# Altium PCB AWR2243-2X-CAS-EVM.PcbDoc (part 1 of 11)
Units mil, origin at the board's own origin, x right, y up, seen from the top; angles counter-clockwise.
Board outline 5118.11 x 3937.01 mil, 8 copper layers (Layer 1 - Top Layer, Layer 2 - GND, Layer 3 - Signal (Sensitive), Layer 4 - GND / Signal, Layer 5 - Signal, Layer 6 - PWR / Signal, Layer 7 - GND, Layer 8 - Bottom Layer), stack 54.8 mil thick; 629 components, 407 nets, 2243 pads, 3950 vias.
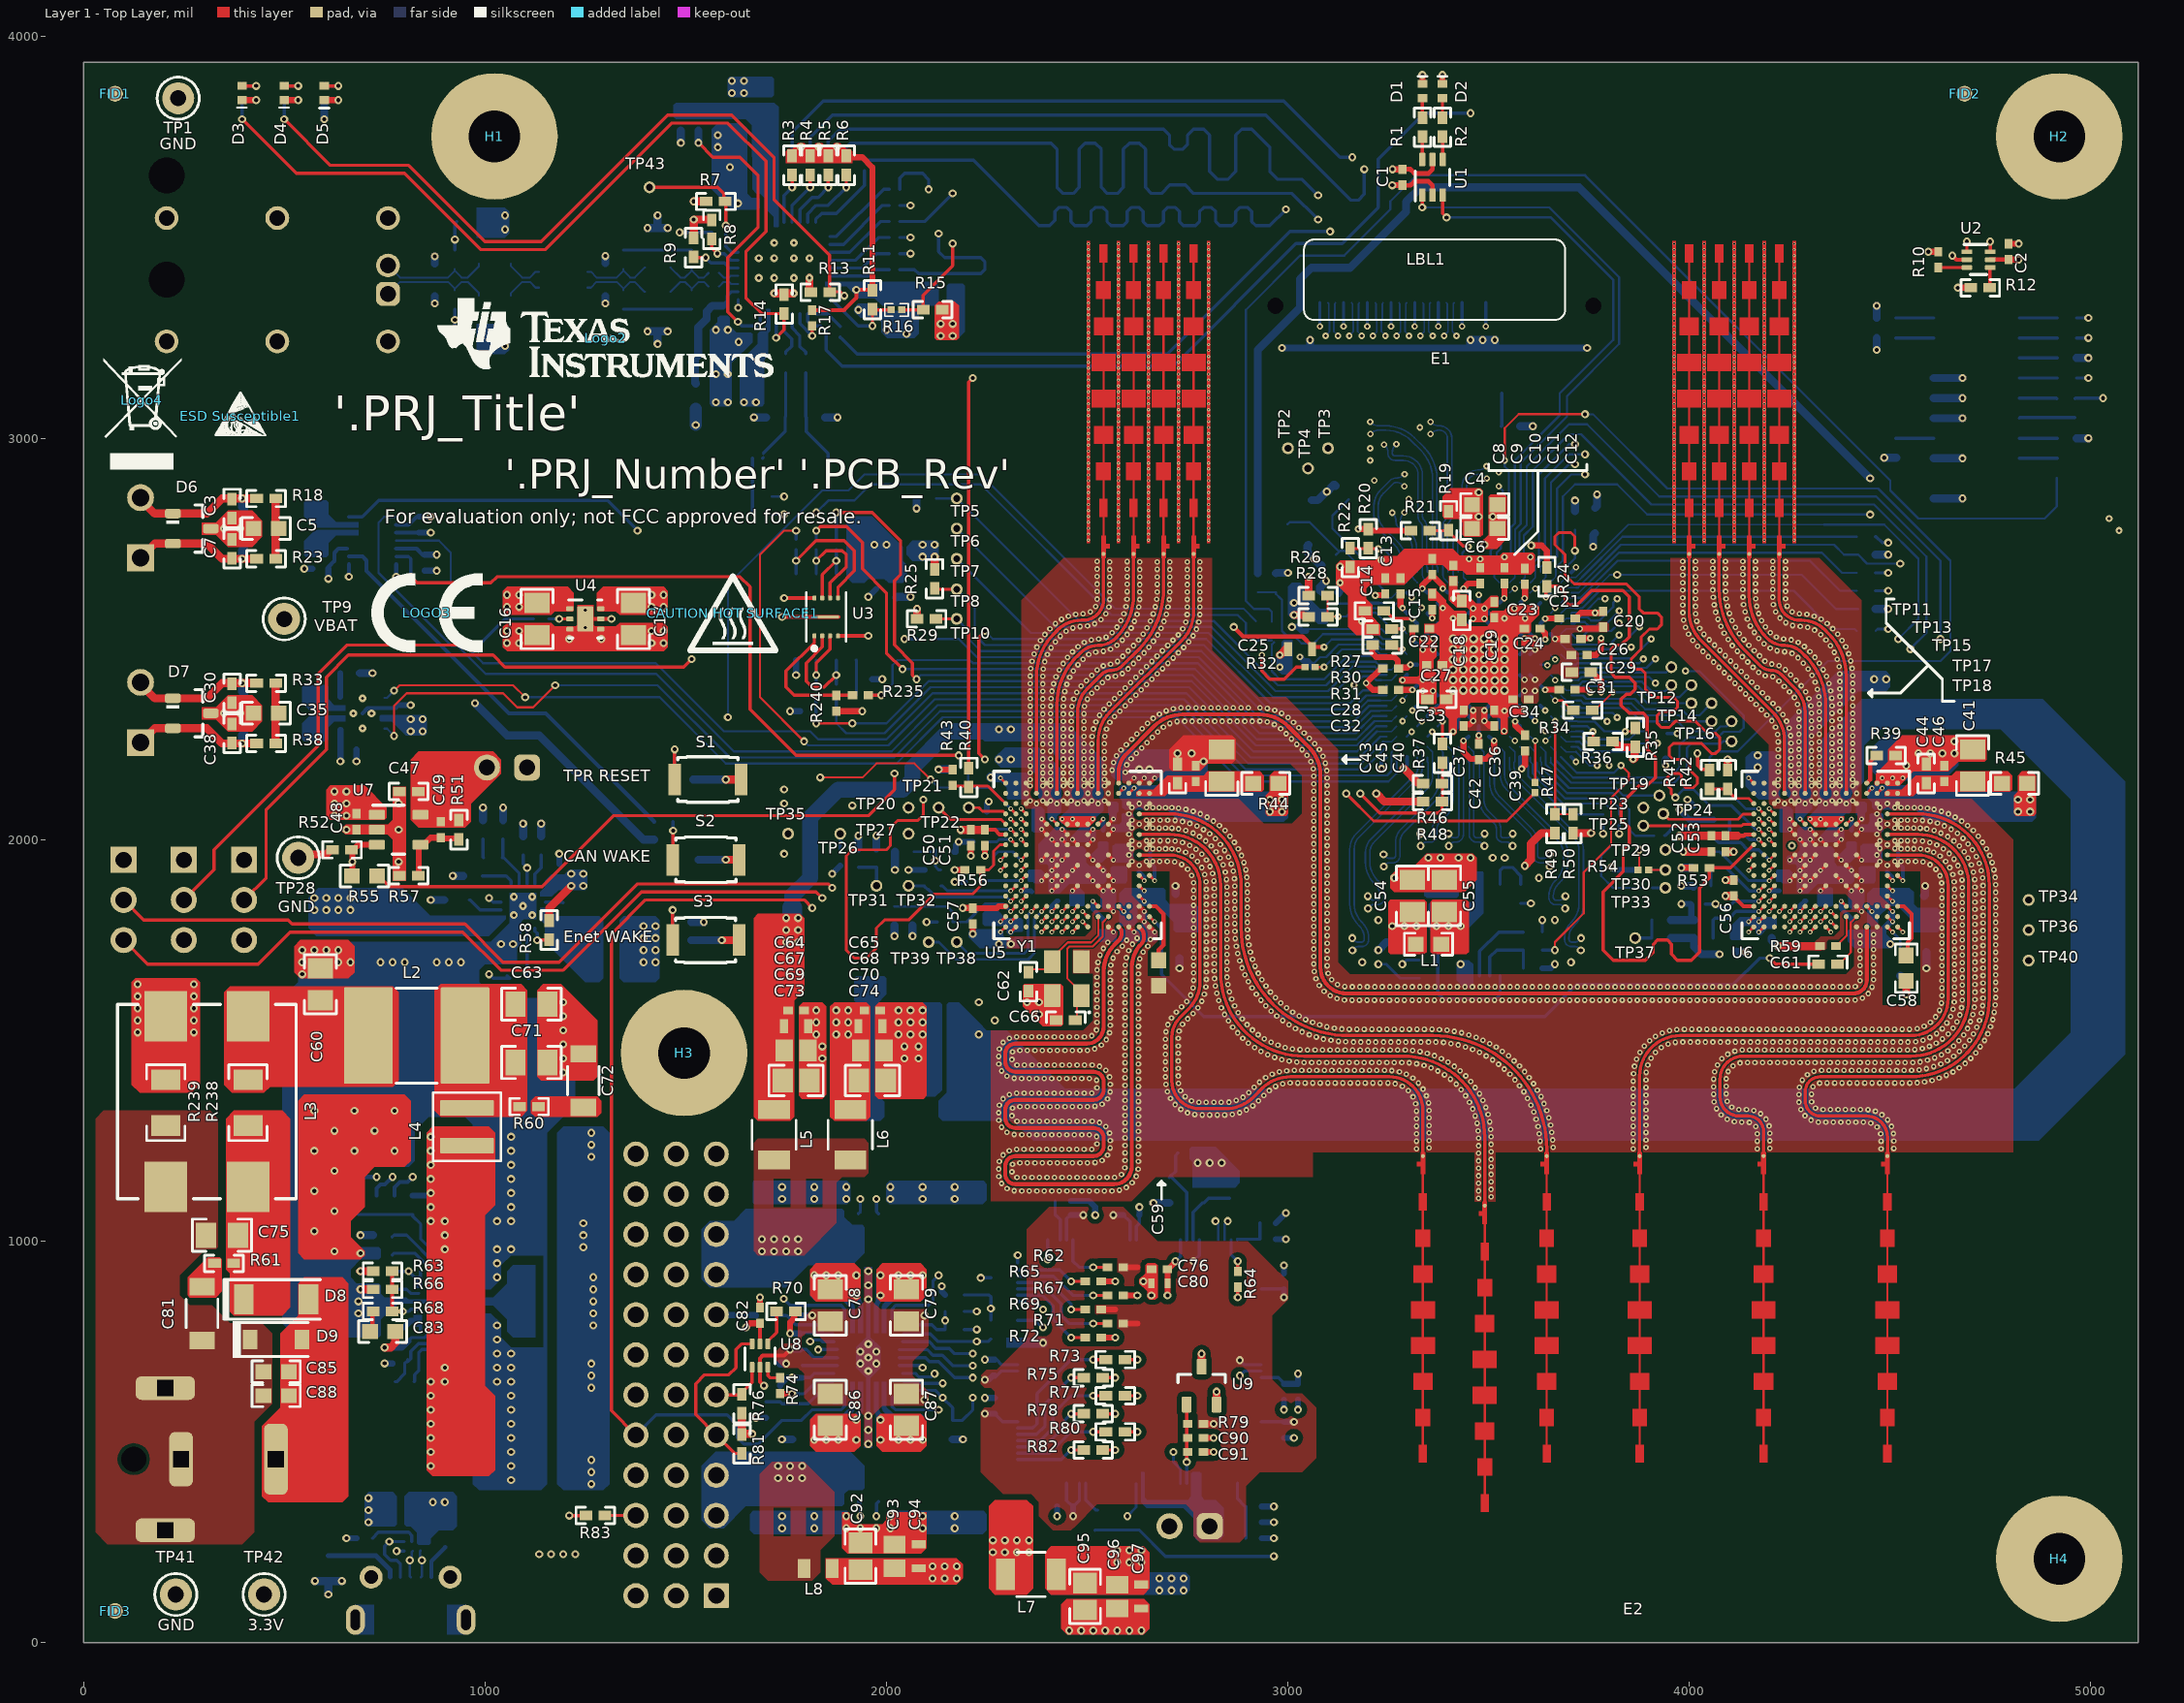
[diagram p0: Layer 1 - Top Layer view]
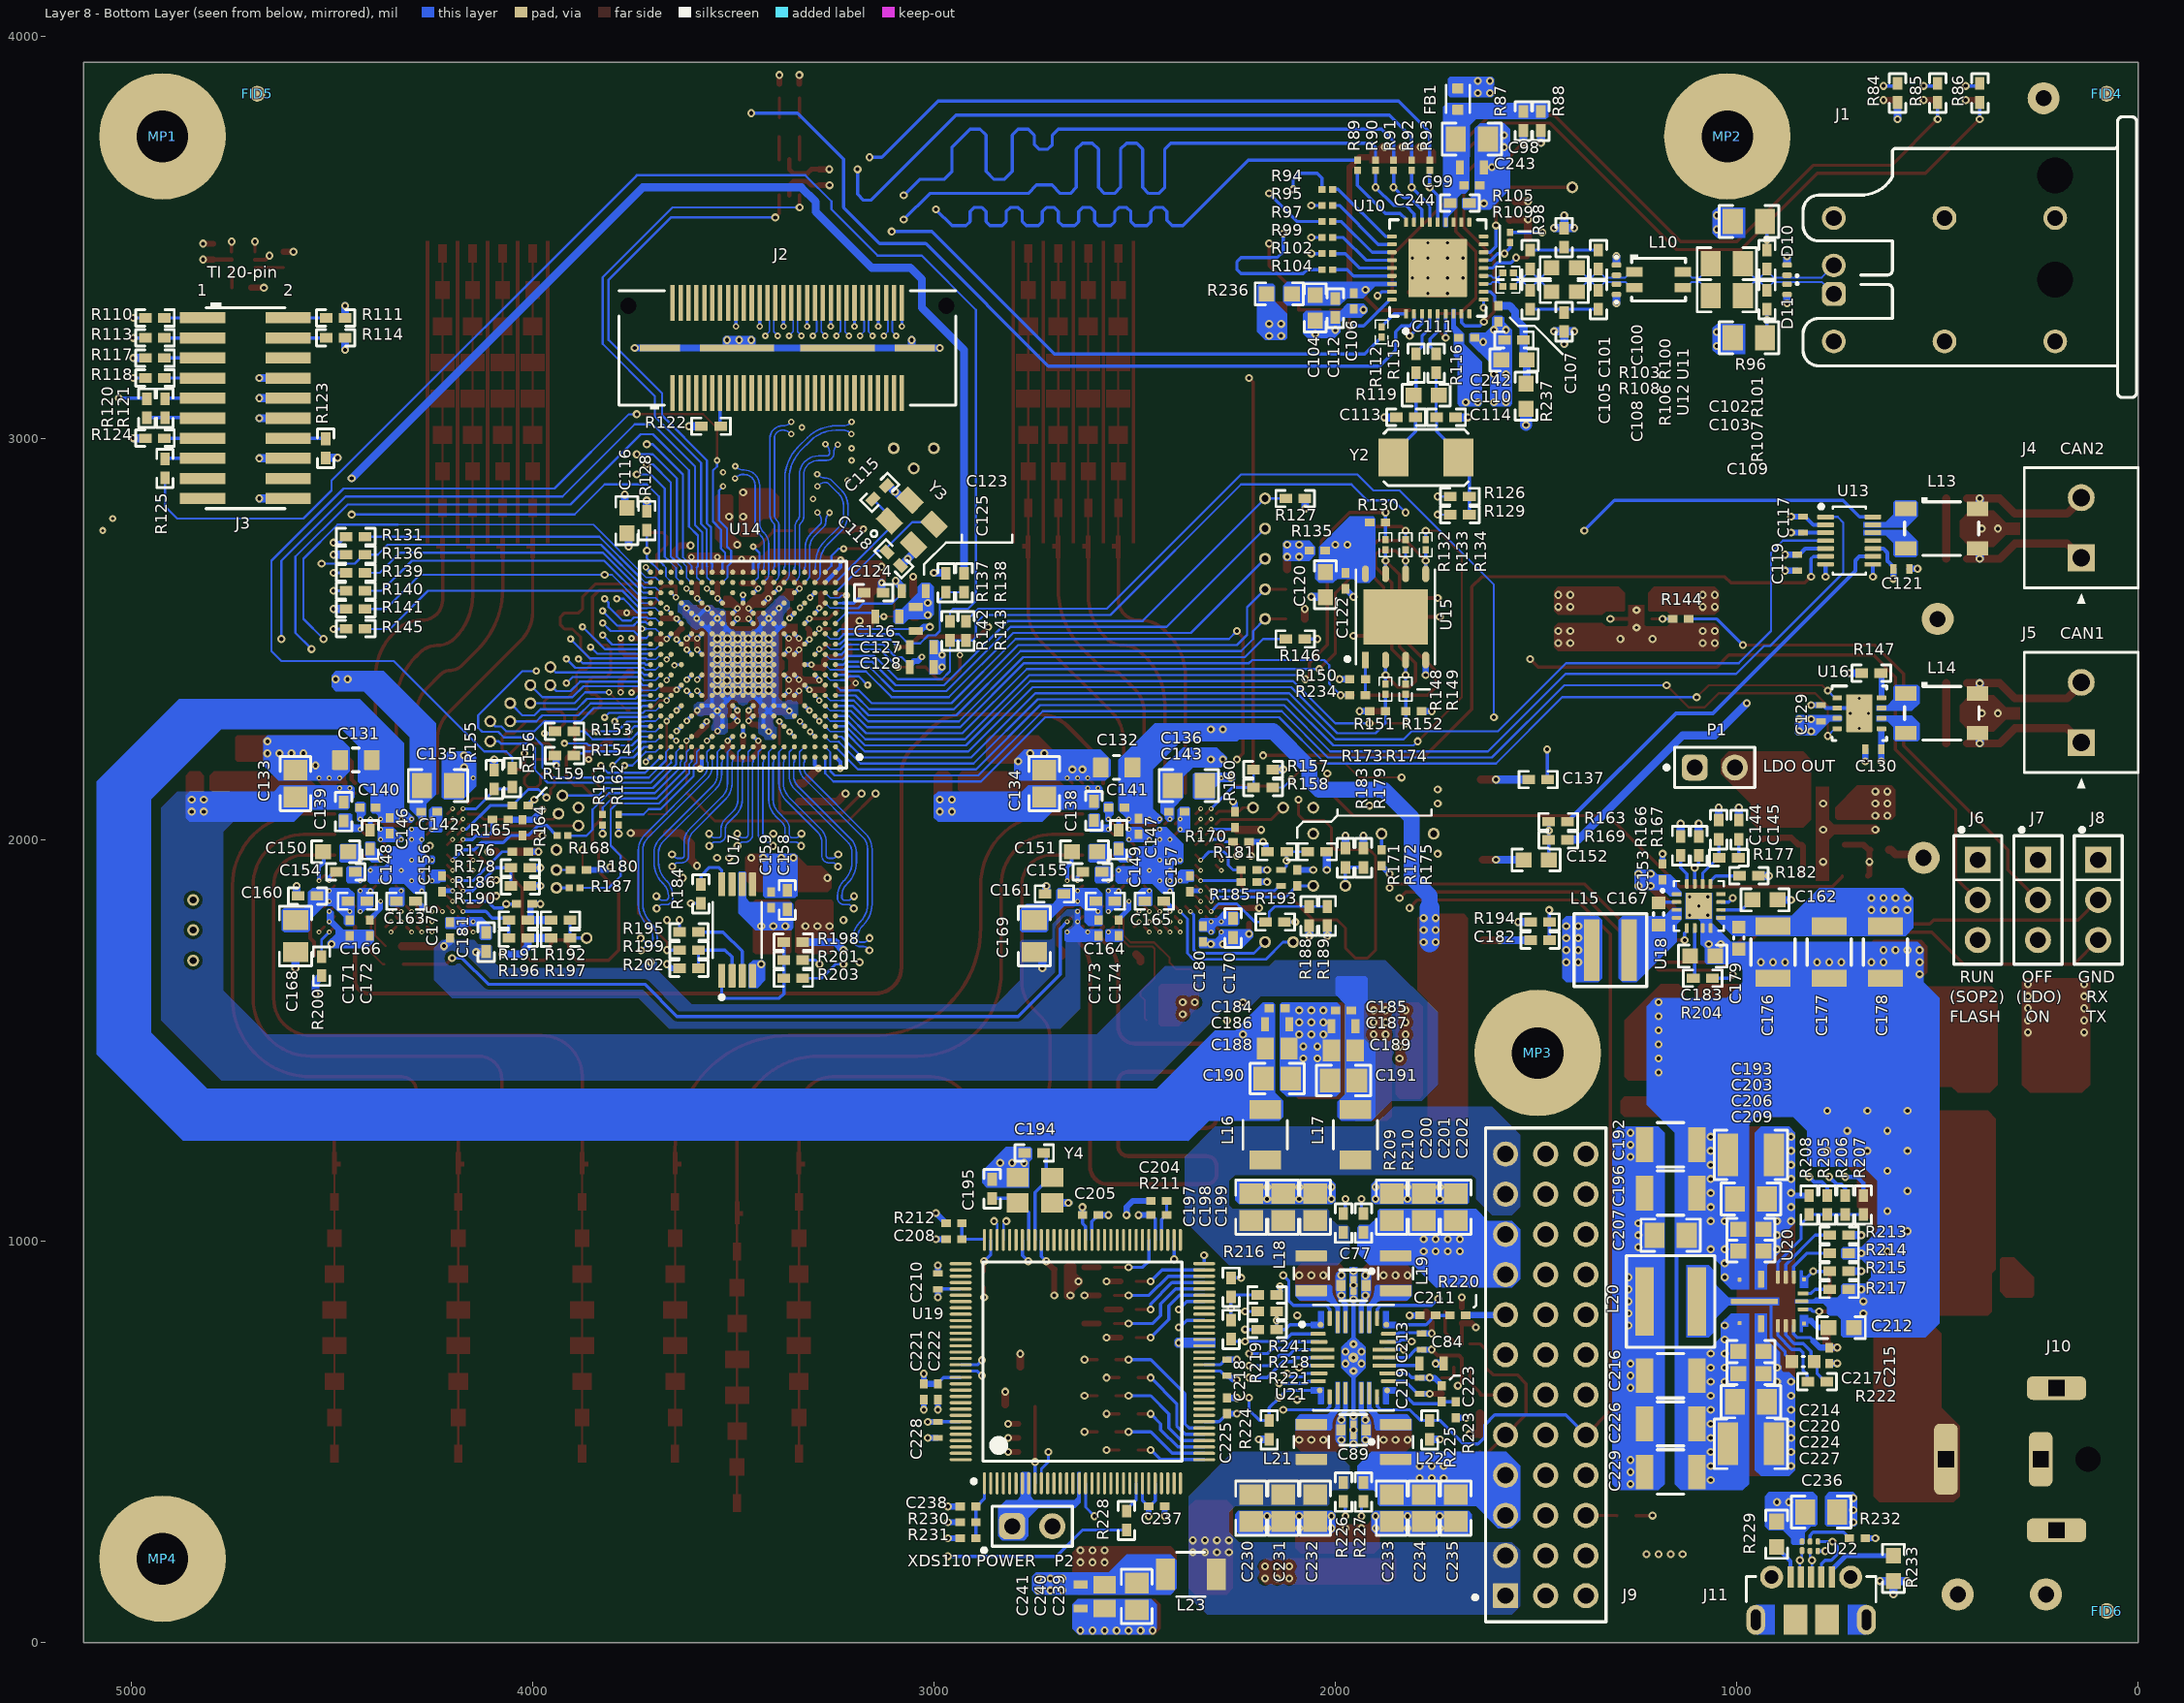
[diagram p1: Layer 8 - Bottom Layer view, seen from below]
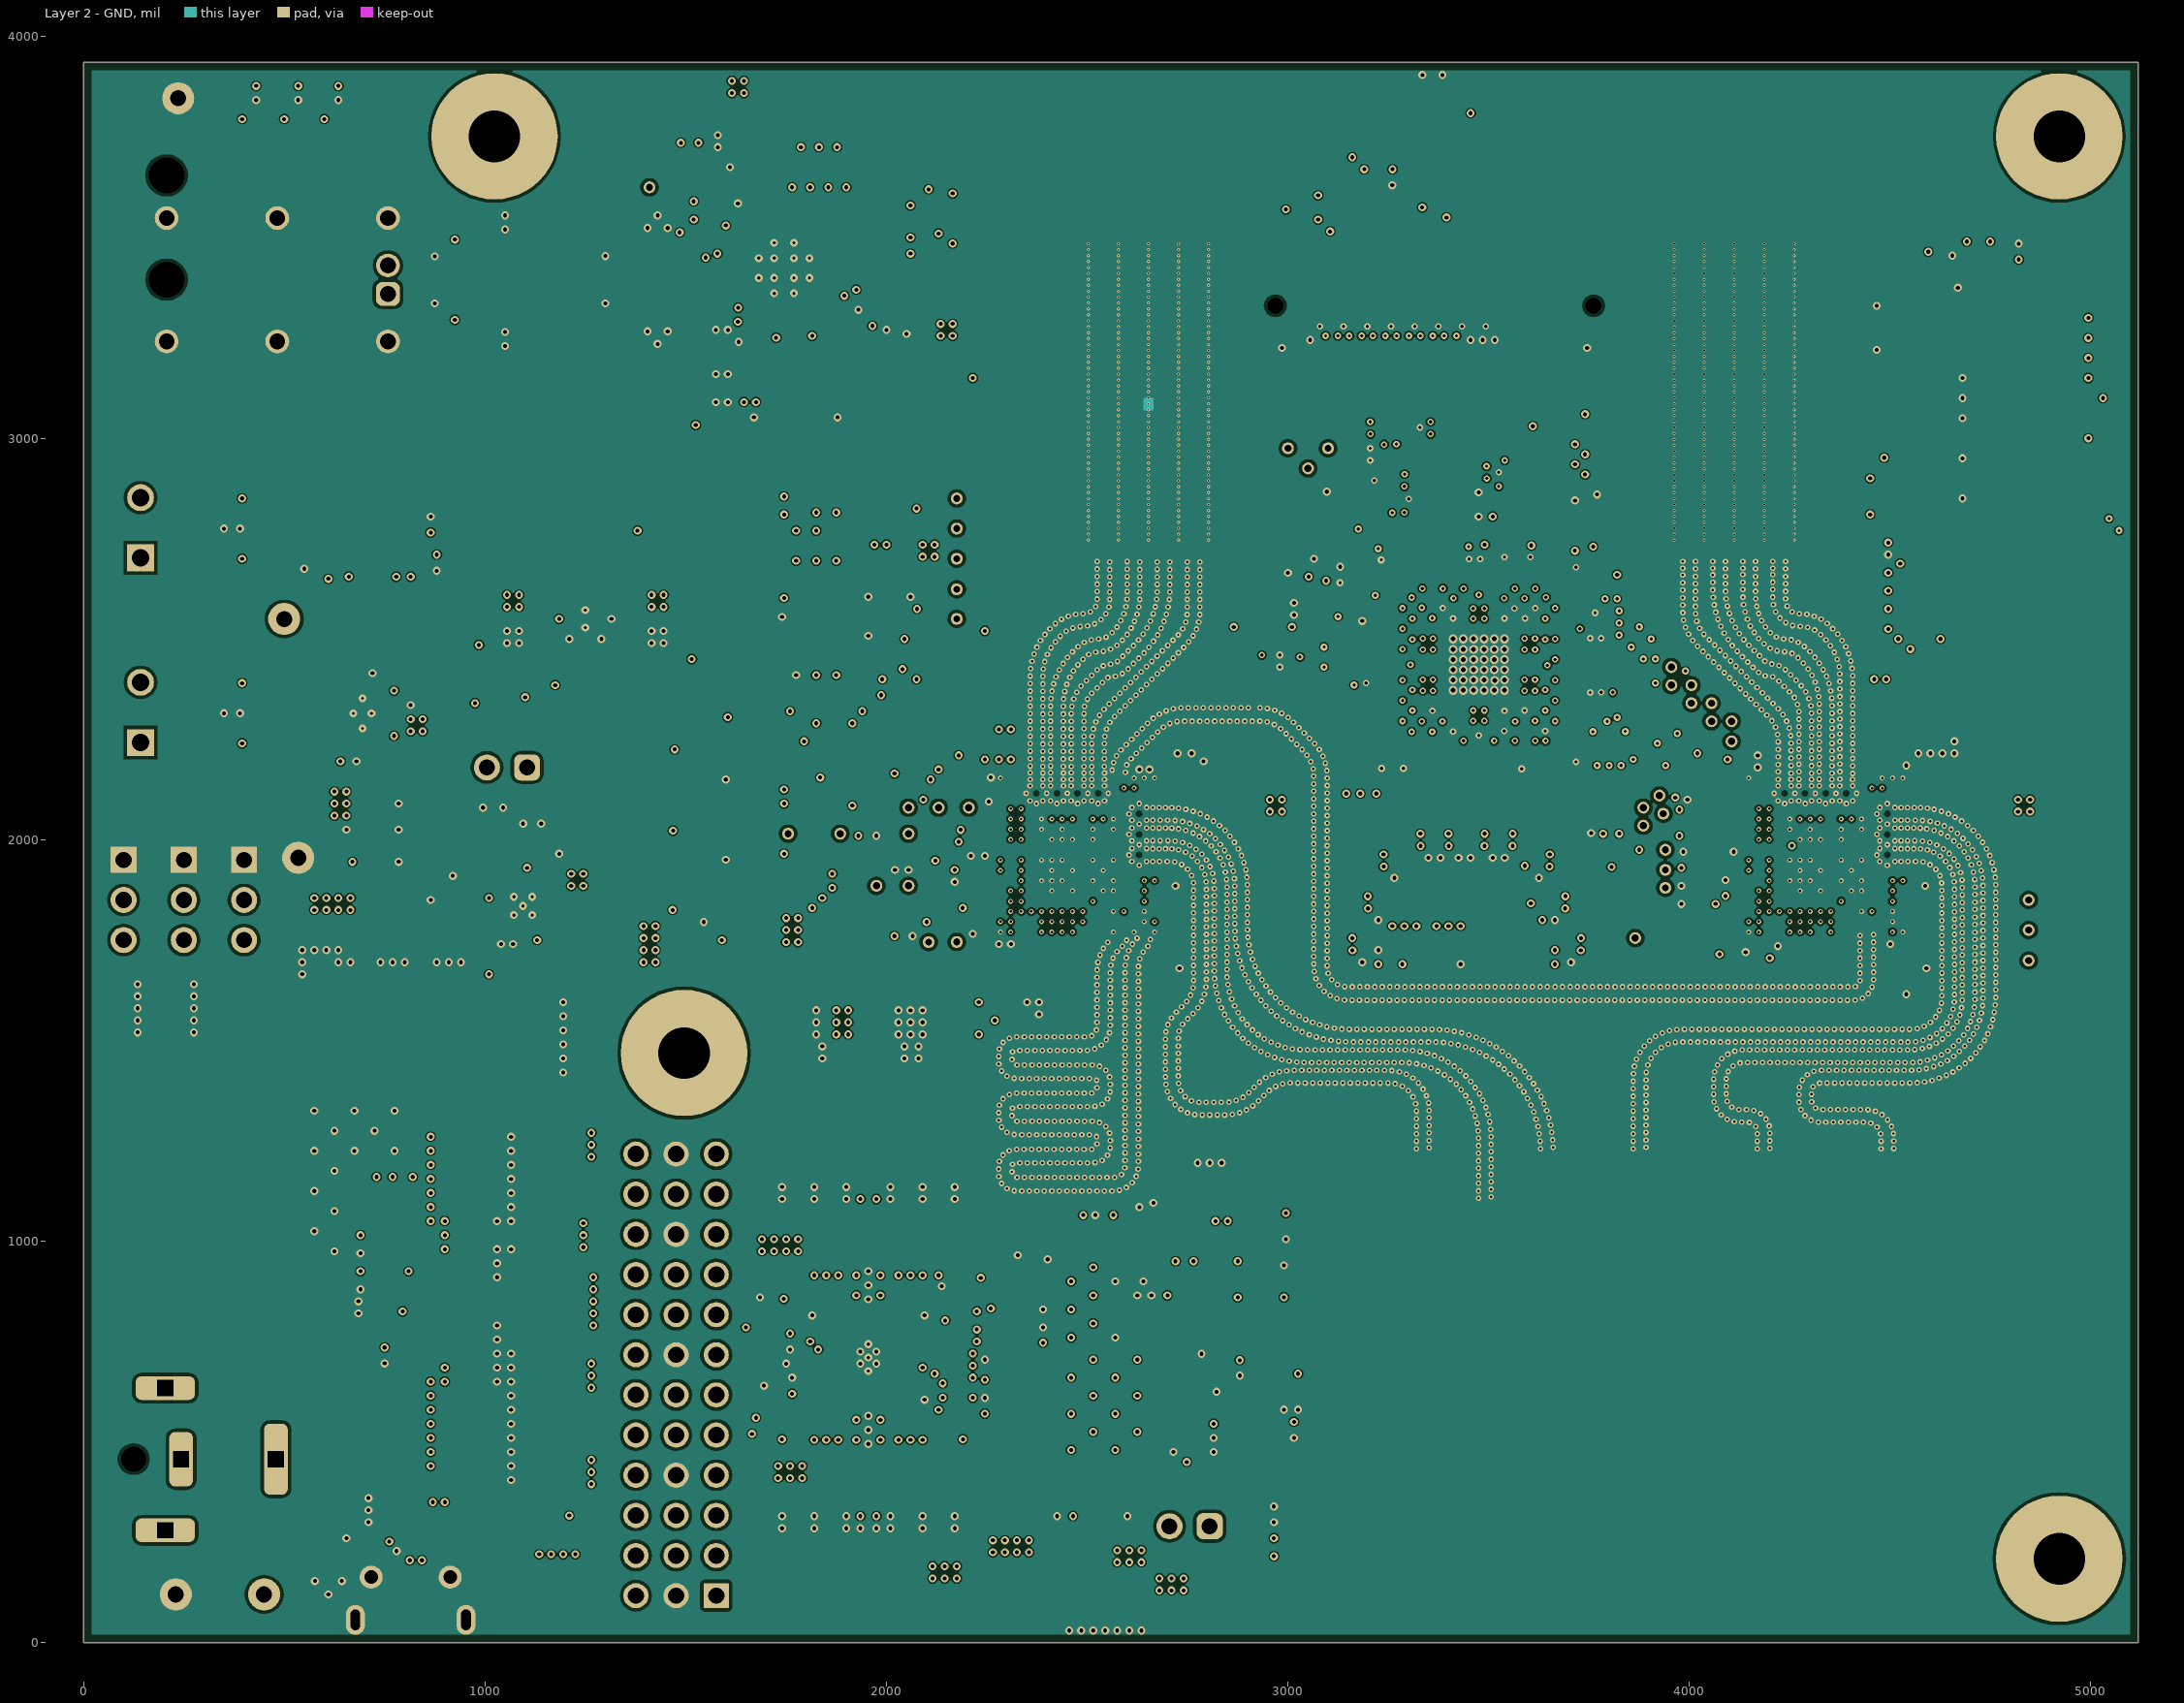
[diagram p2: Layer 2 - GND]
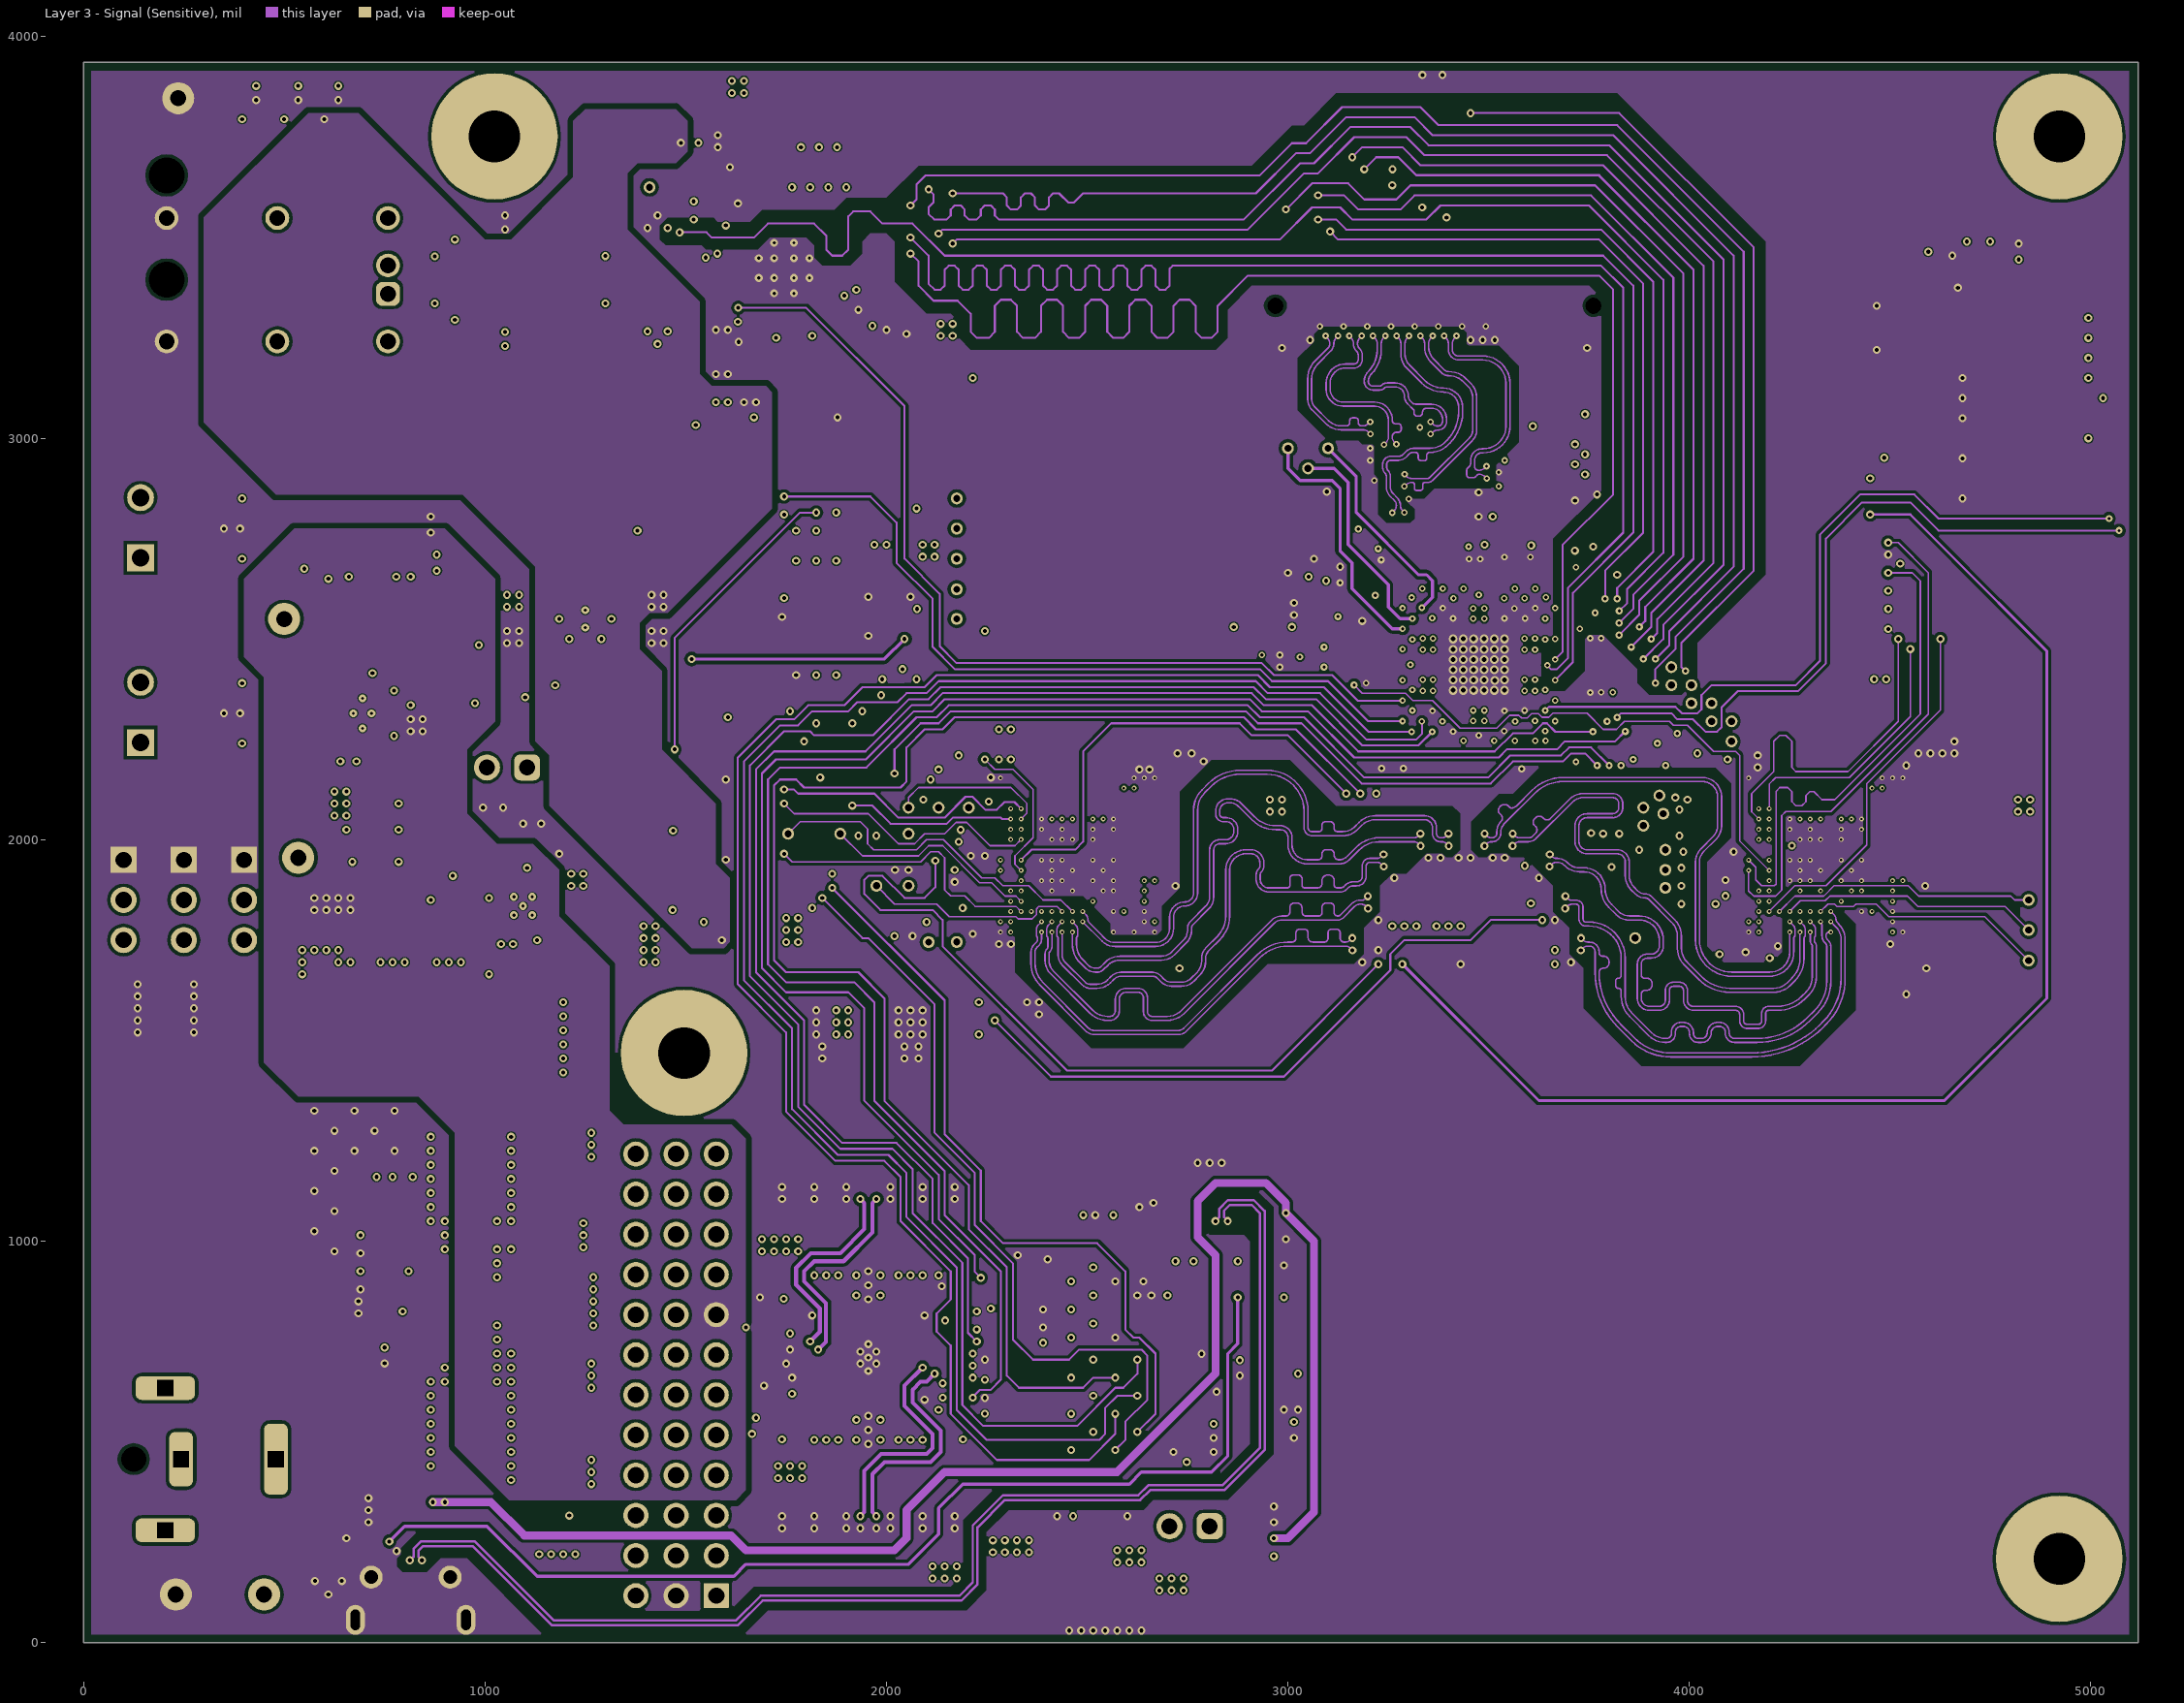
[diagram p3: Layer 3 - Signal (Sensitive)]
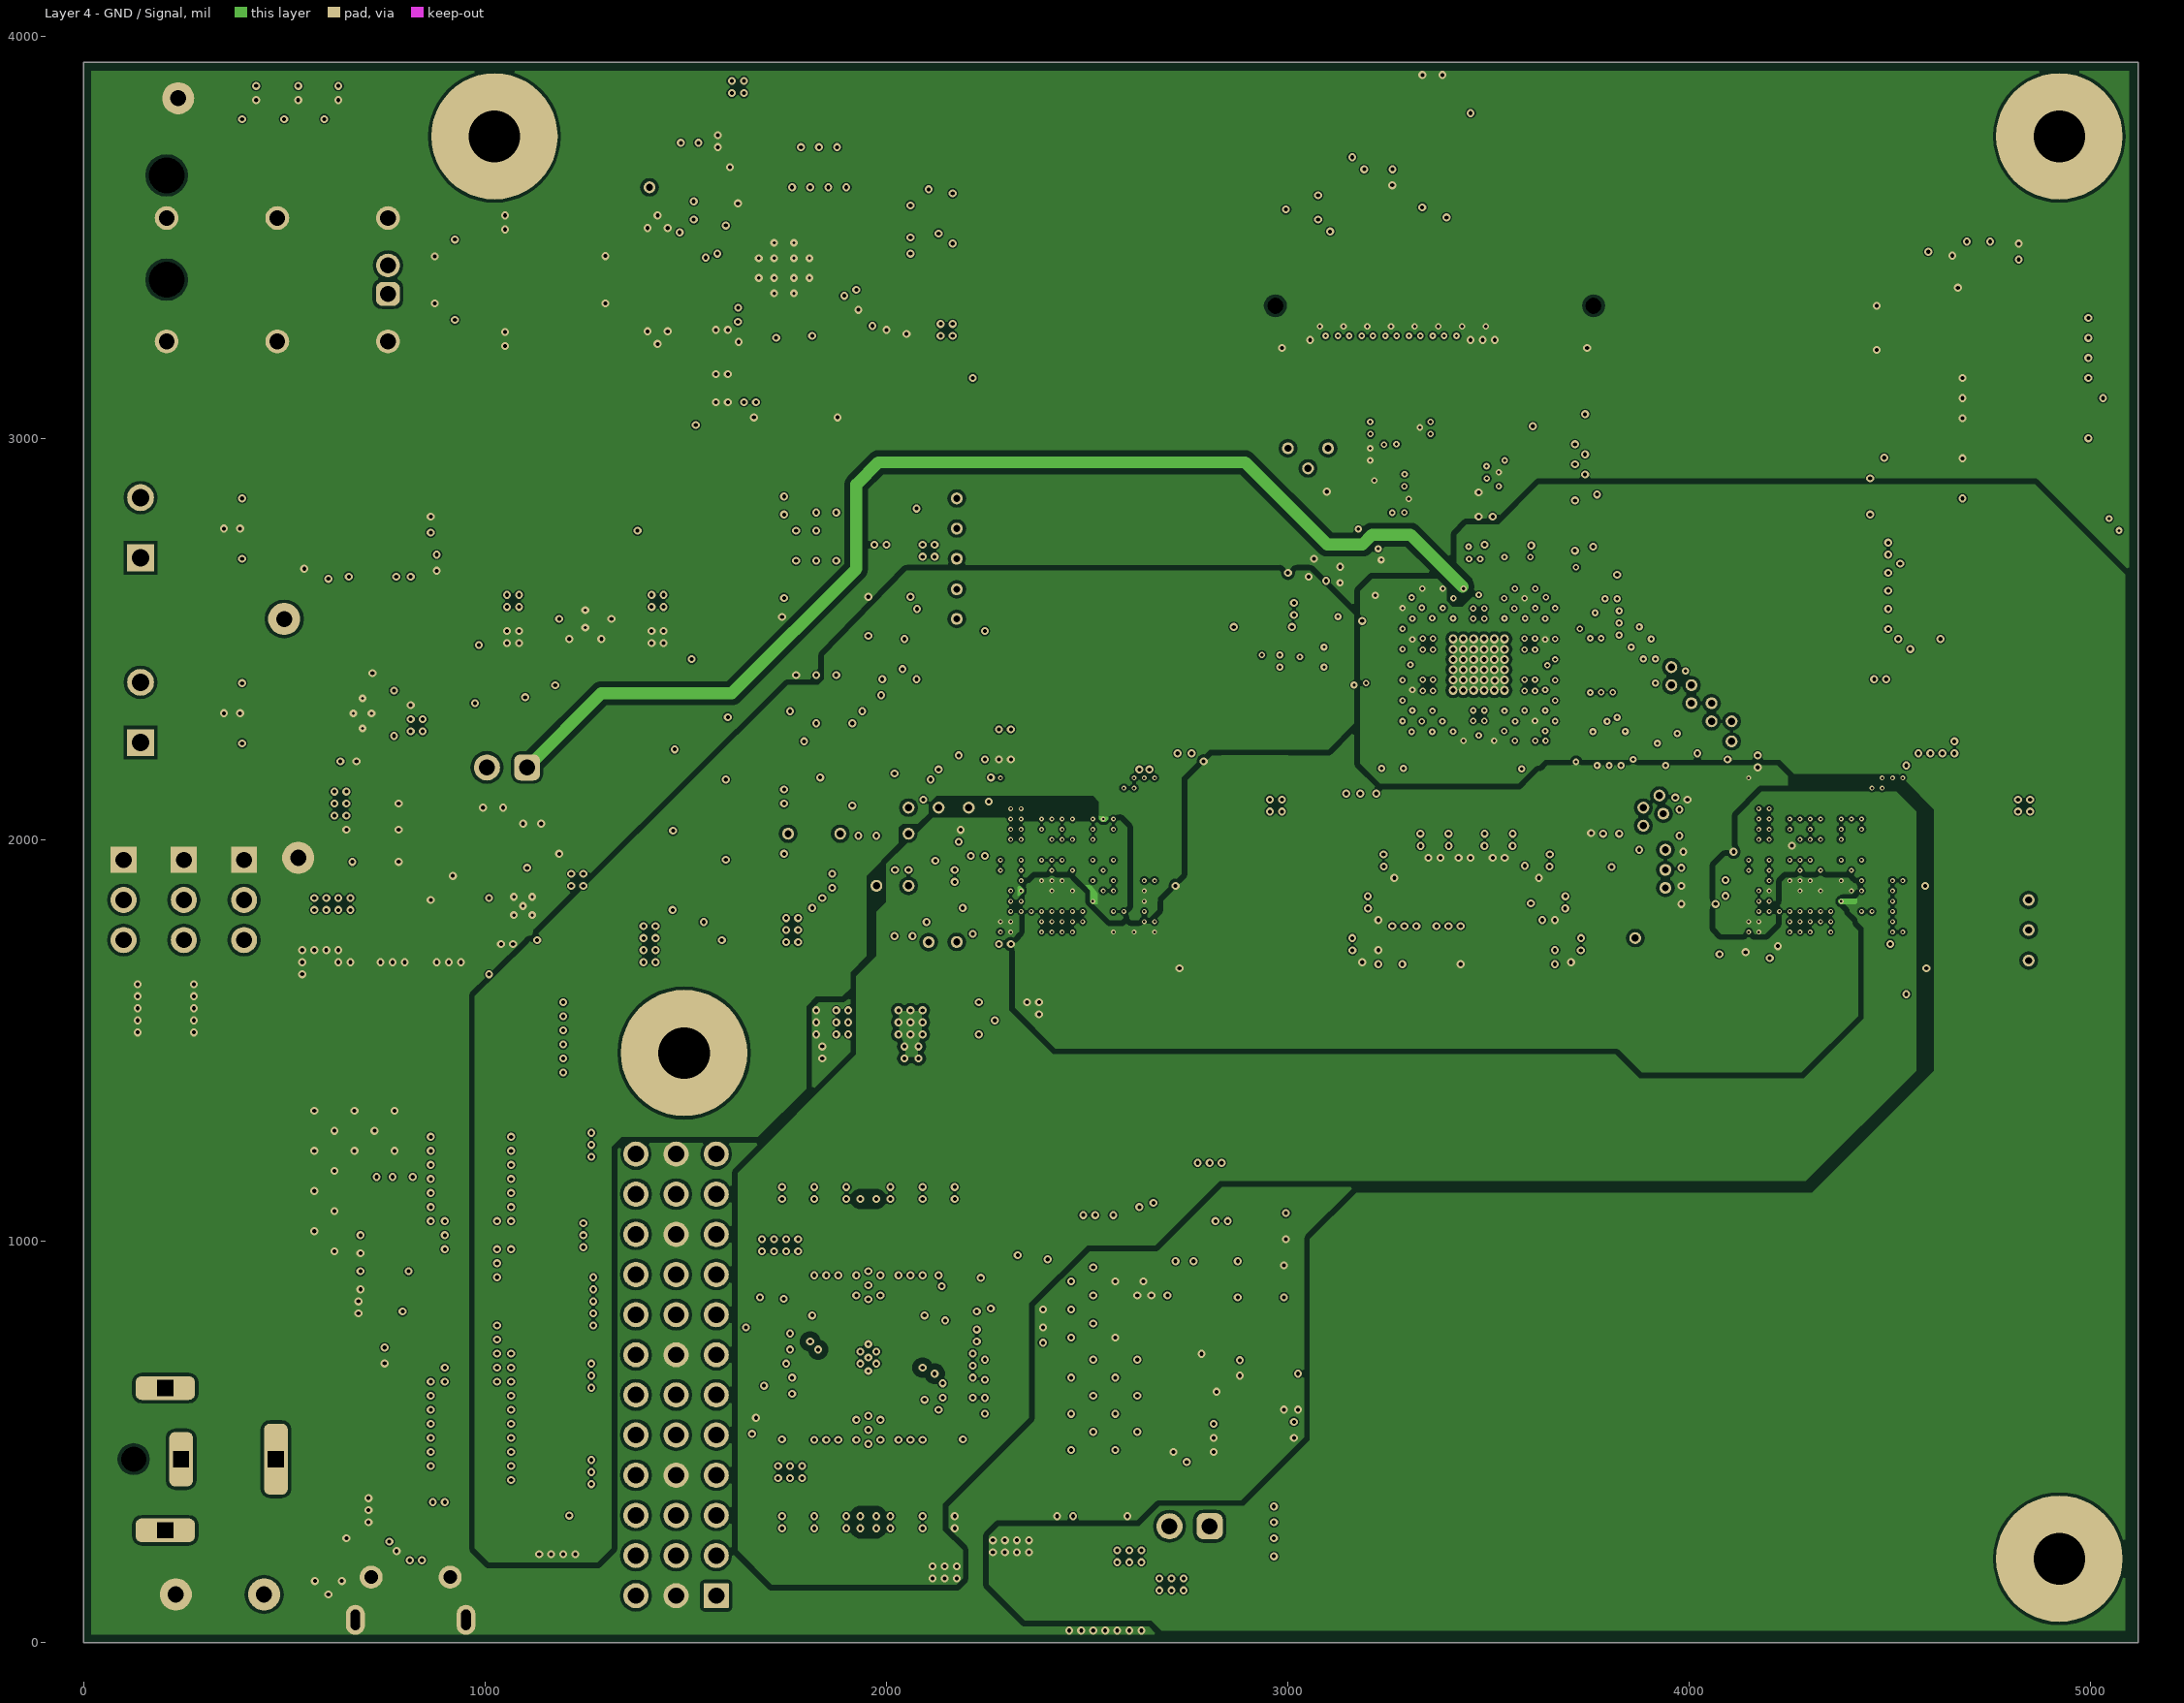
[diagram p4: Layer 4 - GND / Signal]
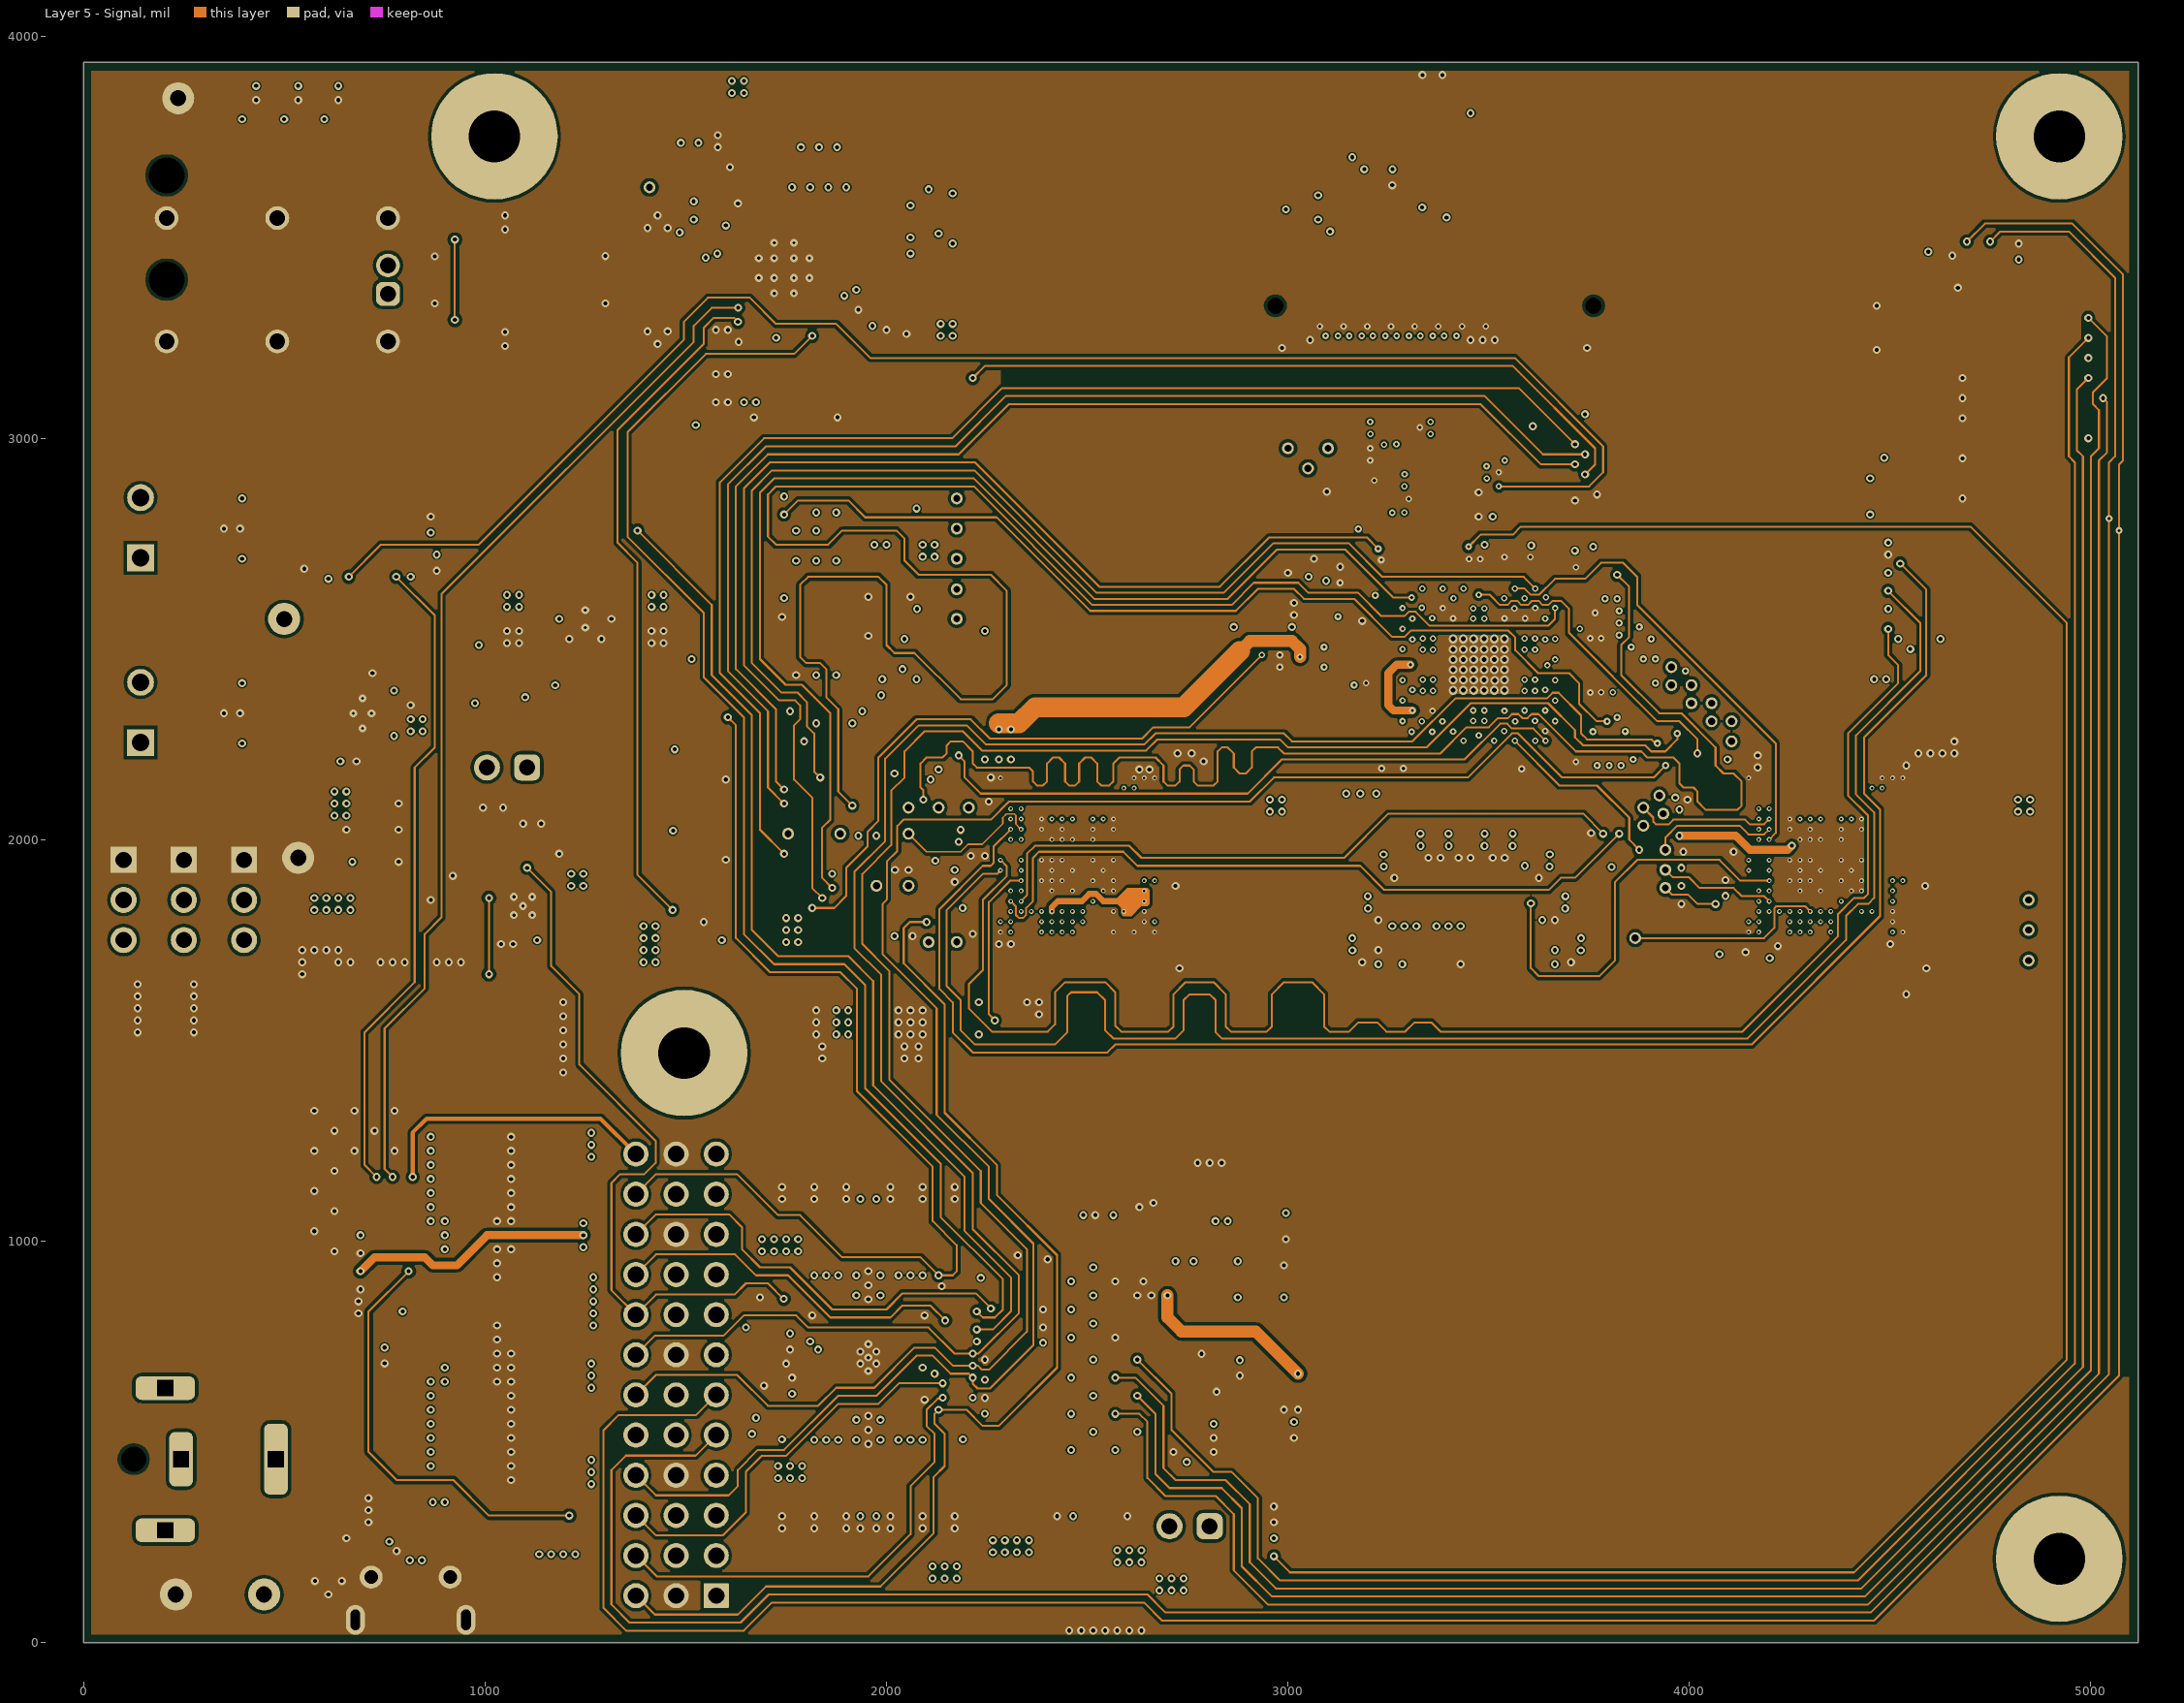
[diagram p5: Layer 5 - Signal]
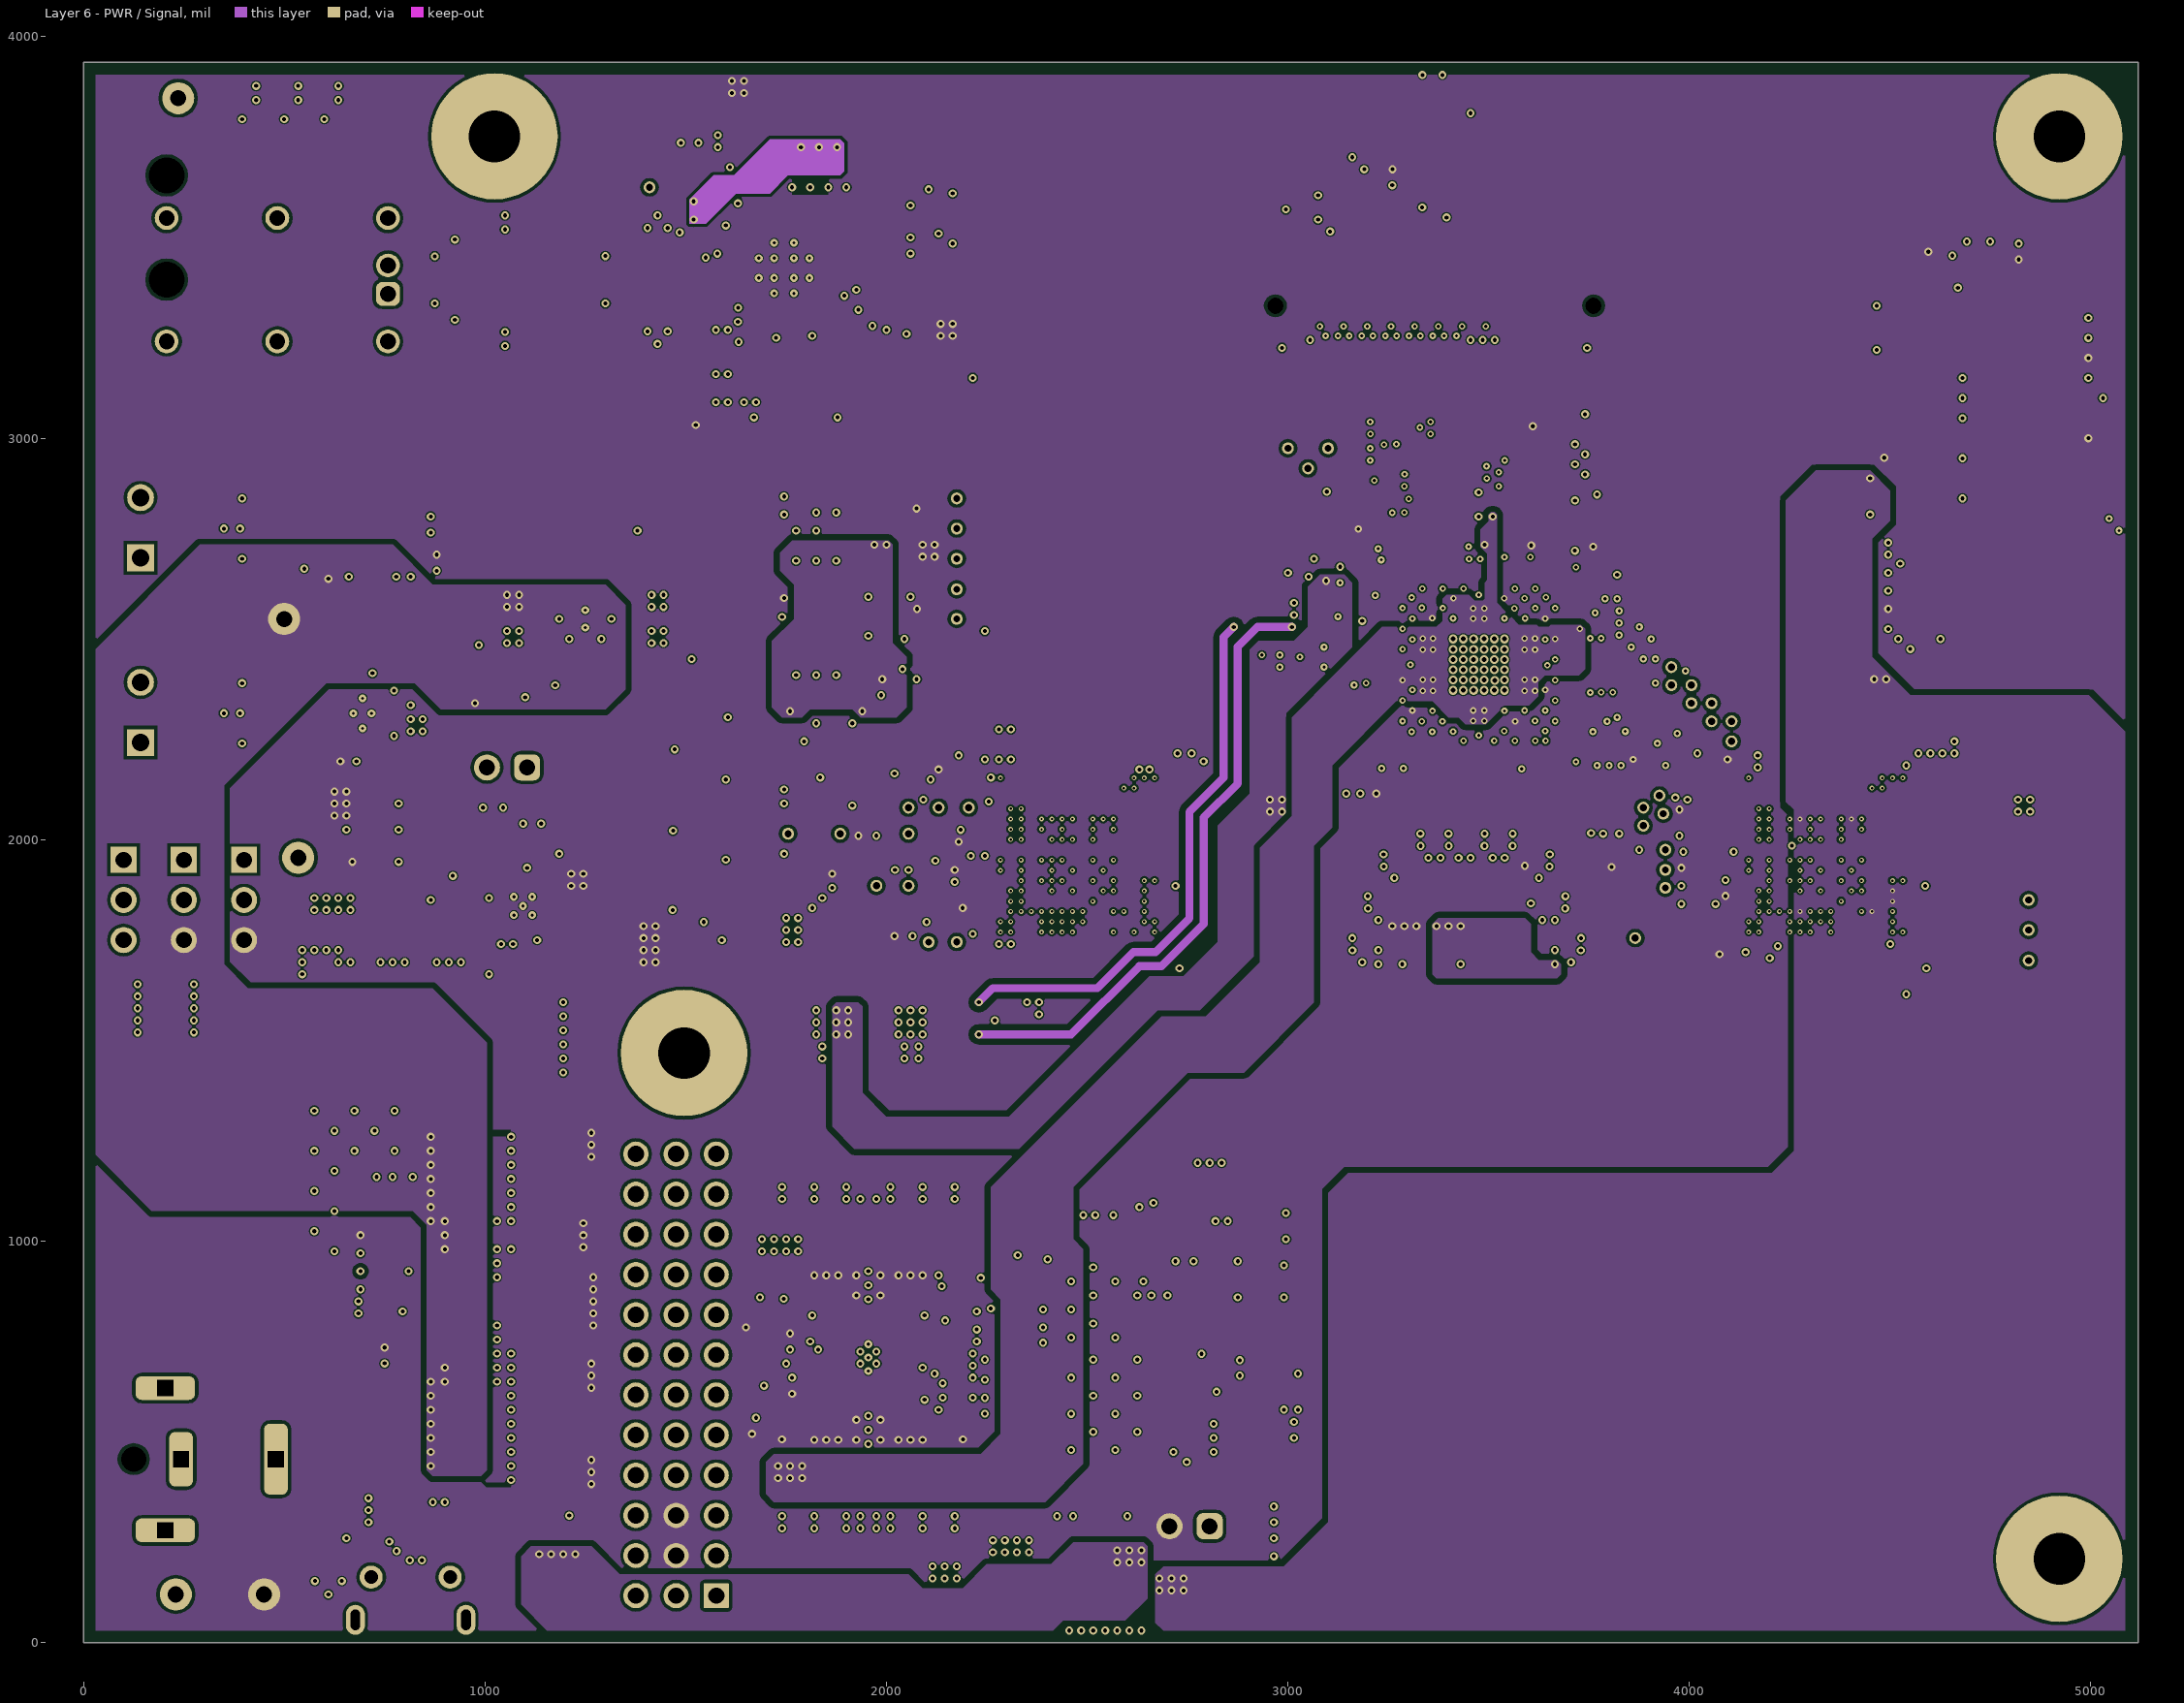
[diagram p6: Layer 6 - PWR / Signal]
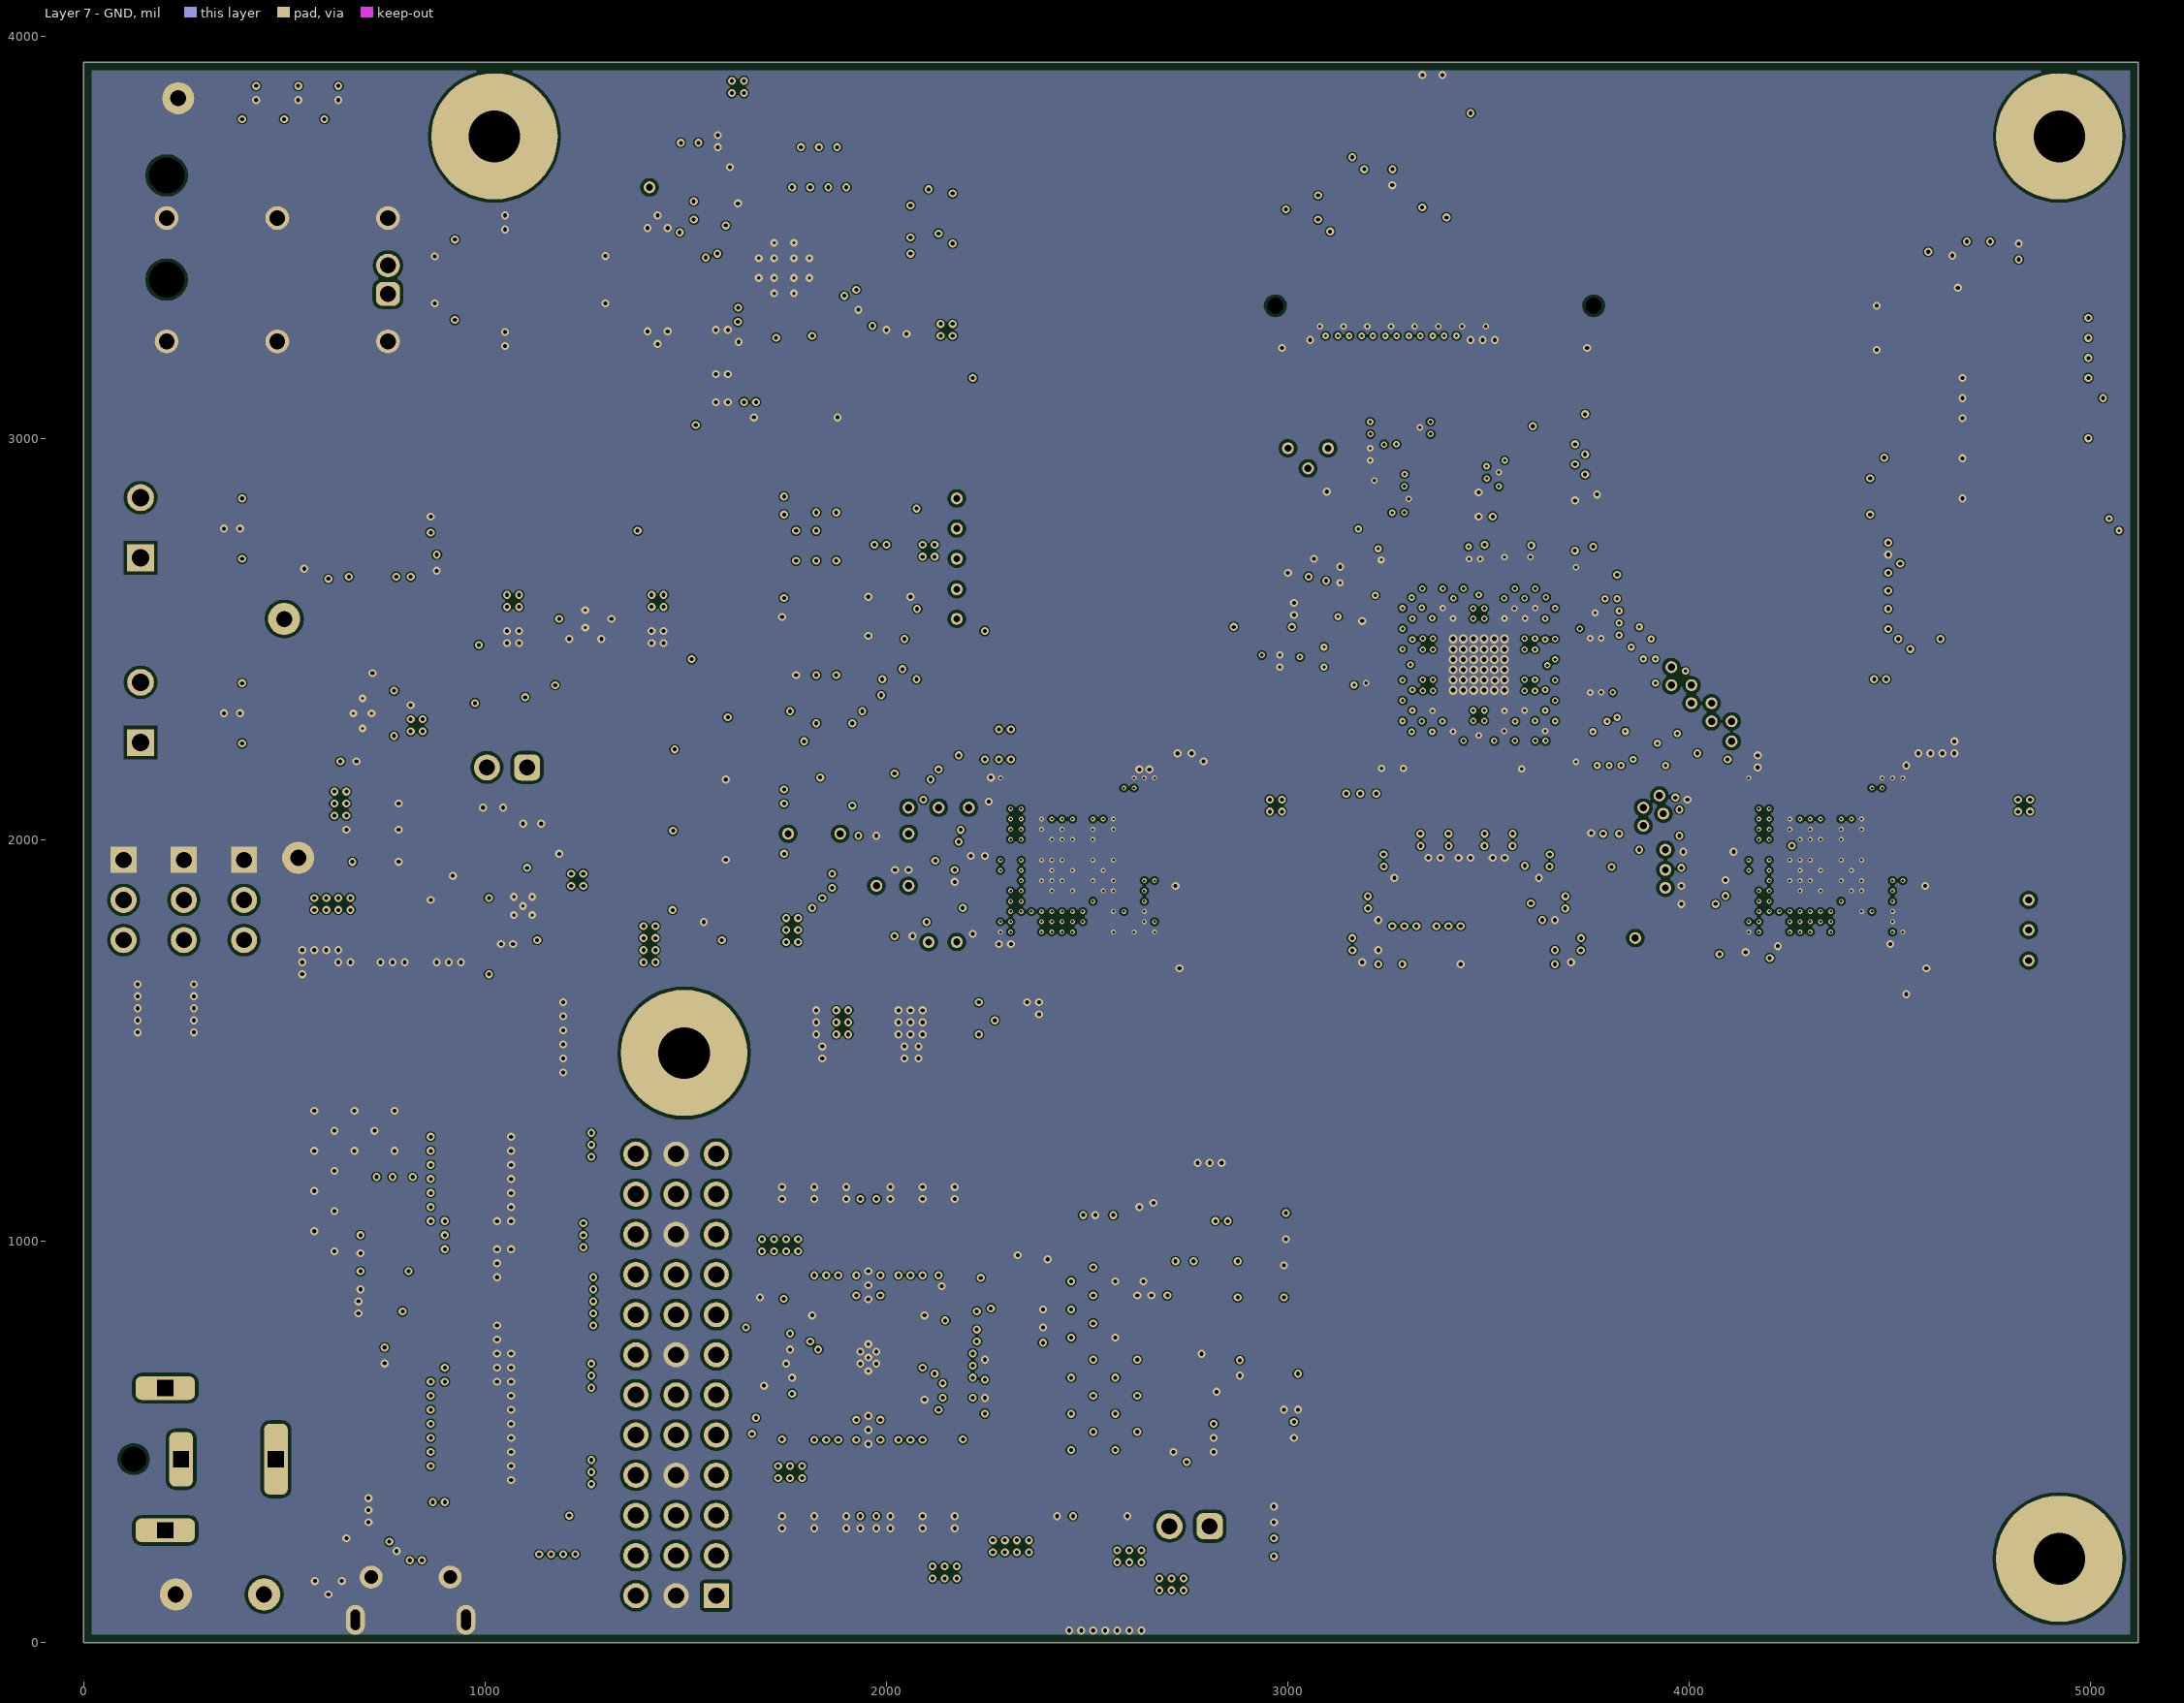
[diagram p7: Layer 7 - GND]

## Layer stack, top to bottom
Top Solder: solder mask 1, Solder Resist, Dk 3.5
Layer 1 - Top Layer: signal copper 1.6
Dielectric 1: core 5, RO3003, Dk 3
Layer 2 - GND: signal copper 1.4
Dielectric 2: prepreg 4.8, 370HR, Dk 4.2
Layer 3 - Signal (Sensitive): signal copper 0.7
Dielectric 3: core 10, 370HR, Dk 3.66
Layer 4 - GND / Signal: signal copper 1.4
Dielectric 4: prepreg 5, 370HR, Dk 4.2
Layer 5 - Signal: signal copper 1.4
Dielectric 5: core 10, 370HR, Dk 4.34
Layer 6 - PWR / Signal: signal copper 0.7
Dielectric 6: prepreg 4.8, 370HR, Dk 4.2
Layer 7 - GND: signal copper 1.4
Dielectric 7: core 5, 370HR, Dk 4.34
Layer 8 - Bottom Layer: signal copper 1.6
Bottom Solder: solder mask 1, Solder Resist, Dk 3.5

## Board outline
0,0 0,3937.01 5118.11,3937.01 5118.11,0

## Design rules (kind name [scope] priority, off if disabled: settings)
AcuteAngle [All] p1: minimum=4.50000000000000E+0001 checktracksonly=TRUE
AssemblyTestPointUsage [All] p1: valid=2
BoardOutlineClearance BoardOutlineClearance_MountingHoles [OnCopper and InComponentClass('Mounting Holes')] p1: gap=25 ignorepadtopadclearanceinfootprint=FALSE
BoardOutlineClearance BoardOutlineClearance_Poly [OnCopper and IsPoly] p2: gap=20 ignorepadtopadclearanceinfootprint=FALSE
BoardOutlineClearance [OnCopper and Not InComponentClass('Logo') and not InComponentClass('FiducialMark') and not InPoly and not TextKind] p3: gap=19 ignorepadtopadclearanceinfootprint=FALSE
Clearance "XDS_3V3 Poly" [InNet('XDS_3V3') And InPoly] p1: gap=12 ignorepadtopadclearanceinfootprint=TRUE
Clearance "Layer 8 Poly" [OnLayer('Layer 8 - Bottom Layer') and InPoly] p2: gap=8 ignorepadtopadclearanceinfootprint=TRUE
Clearance "Layer 7 Poly" [OnLayer('Layer 7 - GND') and InPoly] p3: gap=8 ignorepadtopadclearanceinfootprint=TRUE
Clearance "Layer 6 Poly" [OnLayer('Layer 6 - PWR / Signal') and InPoly] p4: gap=8 ignorepadtopadclearanceinfootprint=TRUE except(15: Track-Poly Poly-Poly)
Clearance "Layer 5 Poly" [OnLayer('Layer 5 - Signal') and InPoly] p5: gap=8 ignorepadtopadclearanceinfootprint=TRUE
Clearance "Layer 4 Poly" [OnLayer('Layer 4 - GND / Signal') and InPoly] p6: gap=8 ignorepadtopadclearanceinfootprint=TRUE except(15: Track-Poly Poly-Poly)
Clearance "Layer 3 Poly" [OnLayer('Layer 3 - Signal (Sensitive)') and InPoly] p7: gap=8 ignorepadtopadclearanceinfootprint=TRUE except(15: Poly-Poly)
Clearance "Layer 2 Poly" [OnLayer('Layer 2 - GND') and InPoly] p8: gap=8 ignorepadtopadclearanceinfootprint=TRUE
Clearance "U22 Poly" [InRegionRelative(3250, 2225, 3700, 2650)] p9: gap=4.02 ignorepadtopadclearanceinfootprint=TRUE
Clearance "Layer 7 Clearance" [OnLayer('Layer 7 - PWR / Signal')] p10: gap=12 ignorepadtopadclearanceinfootprint=TRUE
Clearance Clearance_Poly_U6 [InPolygon vs HasPad('U6-M2') or HasPad('U6-K2') or HasPad('U6-H2') or HasPad('U6-F2') or HasPad('U6-B4') or HasPad('U6-B6') or HasPad('U6-B8')] p11: gap=25 ignorepadtopadclearanceinfootprint=TRUE except(4.02: Track-Poly THPad-Poly Via-Via Via-Fill Via-Poly Via-Region Via-Text Via-Hole Fill-Poly Poly-Poly Poly-Region Poly-Text; 4.17: Arc-Via Arc-Poly Track-Via SMDPad-Via; 6: THPad-Text; 8: Poly-Hole; 9.5: Track-Hole; 9.68: SMDPad-Poly; 12: THPad-THPad THPad-Via THPad-Fill THPad-Region THPad-Hole)
Clearance Clearance_Poly_U5 [InPolygon vs HasPad('U5-M2') or HasPad('U5-K2') or HasPad('U5-H2') or HasPad('U5-F2') or HasPad('U5-B4') or HasPad('U5-B6') or HasPad('U5-B8')] p12: gap=25 ignorepadtopadclearanceinfootprint=TRUE except(4.02: Track-Poly THPad-Poly Via-Via Via-Fill Via-Poly Via-Region Via-Text Via-Hole Fill-Poly Poly-Poly Poly-Region Poly-Text; 4.17: Arc-Via Arc-Poly Track-Via SMDPad-Via; 6: THPad-Text; 8: Poly-Hole; 9.5: Track-Hole; 9.68: SMDPad-Poly; 12: THPad-THPad THPad-Via THPad-Fill THPad-Region THPad-Hole)
Clearance Clearance_Poly [InPolygon] p13: gap=25 ignorepadtopadclearanceinfootprint=TRUE except(4.02: Arc-Poly Track-Poly Via-Via Via-Fill Via-Region Via-Text Via-Hole Poly-Region Poly-Text; 4.17: Arc-Via Track-Via SMDPad-Via SMDPad-Poly THPad-Poly Via-Poly Fill-Poly Poly-Poly; 6: THPad-Text; 8: Poly-Hole; 9.5: Track-Hole; 12: THPad-THPad THPad-Via THPad-Fill THPad-Region THPad-Hole)
Clearance [All] p14: gap=3.9 ignorepadtopadclearanceinfootprint=TRUE
ComponentClearance "TRIPAD COMPONENTS" [not InComponentClass('TRIPAD RESISTORS')] p1: gap=0 collisioncheckmode=3 verticalgap=0 showdistances=FALSE
ComponentClearance ComponentClearance_MountingHoles_FiducialMarks [InComponentClass('Mounting Holes') vs InComponentClass('FiducialMark')] p2: gap=50 collisioncheckmode=3 verticalgap=10 showdistances=FALSE
ComponentClearance ComponentClearance_Shunt [InComponentClass('Header') vs InComponentClass('Shunt')] p3: gap=0 collisioncheckmode=3 verticalgap=0 showdistances=FALSE
ComponentClearance ComponentClearance_Logo [InComponentClass('Logo')] p4: gap=50 collisioncheckmode=3 verticalgap=10 showdistances=FALSE
ComponentClearance ComponentClearance_MountingHoles [InComponentClass('Mounting Holes')] p5: gap=250 collisioncheckmode=3 verticalgap=100000 showdistances=FALSE
ComponentClearance ComponentClearance_SmallPassives [HasFootprint('0201*') or  HasFootprint('0508') or HasFootprint('0603*') or HasFootprint('0612') or HasFootprint('0805*') or HasFootprint('0815*') or HasFootprint('0830*') or HasFootprint('1206*') or HasFootprint('1210*') or HasFootprint('1808*') or HasFootprint('1812*') or HasFootprint('1825*') or HasFootprint('2010*') or HasFootprint('2220*') or HasFootprint('2225*') or HasFootprint('2512*') or HasFootprint('2728*') or HasFootprint('3518*') vs HasFootprint('0201*') or HasFootprint('0508') or HasFootprint('0603*') or HasFootprint('0612') or HasFootprint('0805*') or HasFootprint('0815*') or HasFootprint('0830*') or HasFootprint('1206*') or HasFootprint('1210*') or HasFootprint('1808*') or HasFootprint('1812*') or HasFootprint('1825*') or HasFootprint('2010*') or HasFootprint('2220*') or HasFootprint('2225*') or HasFootprint('2512*') or HasFootprint('2728*') or HasFootprint('3518*')] p6: gap=5 collisioncheckmode=3 verticalgap=5 showdistances=FALSE
ComponentClearance ComponentClearance_THtoSMT [IsThruComponent vs IsSMTComponent] p7: gap=10 collisioncheckmode=3 verticalgap=10 showdistances=FALSE
ComponentClearance ComponentClearance_THtoTH [IsThruComponent vs IsThruComponent] p8: gap=20 collisioncheckmode=3 verticalgap=10 showdistances=FALSE
ComponentClearance ComponentClearance_ScrewToNut [(HasFootprint('NY PMS 440 0025 PH')) vs (HasFootprint('Keystone_1902C'))] p9: gap=5 collisioncheckmode=3 verticalgap=10 showdistances=FALSE
ComponentClearance [All] p10: gap=0 collisioncheckmode=3 verticalgap=0 showdistances=FALSE
DiffPairsRouting DiffPairsRouting_100E [InDifferentialPairClass('DIFF_100E')] p1: maxlimit=8 minlimit=1 mostfreqgap=8 toplayer_mingap=7 toplayer_maxgap=7 toplayer_prefgap=7 toplayer_minwidth=4 toplayer_maxwidth=4 toplayer_prefwidth=4 midlayer1_mingap=5 midlayer1_maxgap=5 midlayer1_prefgap=5 midlayer1_minwidth=5 midlayer1_maxwidth=5 midlayer1_prefwidth=5 midlayer2_maxgap=1 midlayer2_prefgap=1 midlayer2_minwidth=1 midlayer2_maxwidth=1 midlayer2_prefwidth=1 midlayer3_maxgap=1 midlayer3_prefgap=1 midlayer3_minwidth=1 midlayer3_maxwidth=1 midlayer3_prefwidth=1 midlayer4_maxgap=1 midlayer4_prefgap=1 midlayer4_minwidth=1 midlayer4_maxwidth=1 midlayer4_prefwidth=1 midlayer6_mingap=8 midlayer6_minwidth=4 midlayer6_maxwidth=4 midlayer6_prefwidth=4 midlayer7_mingap=8 midlayer7_minwidth=4 midlayer7_maxwidth=4 midlayer7_prefwidth=4 bottomlayer_mingap=7 bottomlayer_maxgap=7 bottomlayer_prefgap=7 bottomlayer_minwidth=4 bottomlayer_maxwidth=4 bottomlayer_prefwidth=4 substack1={9319A519-0D26-40B3-8AF8-C4998BECF1C7} toplayer_{9319a519-0d26-40b3-8af8-c4998becf1c7}_minwidth=15 toplayer_{9319a519-0d26-40b3-8af8-c4998becf1c7}_maxwidth=15 toplayer_{9319a519-0d26-40b3-8af8-c4998becf1c7}_prefwidth=15 midlayer1_{9319a519-0d26-40b3-8af8-c4998becf1c7}_minwidth=15 midlayer1_{9319a519-0d26-40b3-8af8-c4998becf1c7}_maxwidth=15 midlayer1_{9319a519-0d26-40b3-8af8-c4998becf1c7}_prefwidth=15 midlayer2_{9319a519-0d26-40b3-8af8-c4998becf1c7}_minwidth=15 midlayer2_{9319a519-0d26-40b3-8af8-c4998becf1c7}_maxwidth=15 midlayer2_{9319a519-0d26-40b3-8af8-c4998becf1c7}_prefwidth=15 midlayer3_{9319a519-0d26-40b3-8af8-c4998becf1c7}_minwidth=15 midlayer3_{9319a519-0d26-40b3-8af8-c4998becf1c7}_maxwidth=15 midlayer3_{9319a519-0d26-40b3-8af8-c4998becf1c7}_prefwidth=15 midlayer4_{9319a519-0d26-40b3-8af8-c4998becf1c7}_minwidth=15 midlayer4_{9319a519-0d26-40b3-8af8-c4998becf1c7}_maxwidth=15 midlayer4_{9319a519-0d26-40b3-8af8-c4998becf1c7}_prefwidth=15 midlayer6_{9319a519-0d26-40b3-8af8-c4998becf1c7}_minwidth=15 midlayer6_{9319a519-0d26-40b3-8af8-c4998becf1c7}_maxwidth=15 midlayer6_{9319a519-0d26-40b3-8af8-c4998becf1c7}_prefwidth=15 midlayer7_{9319a519-0d26-40b3-8af8-c4998becf1c7}_minwidth=15 midlayer7_{9319a519-0d26-40b3-8af8-c4998becf1c7}_maxwidth=15 midlayer7_{9319a519-0d26-40b3-8af8-c4998becf1c7}_prefwidth=15 bottomlayer_{9319a519-0d26-40b3-8af8-c4998becf1c7}_minwidth=15 bottomlayer_{9319a519-0d26-40b3-8af8-c4998becf1c7}_maxwidth=15 bottomlayer_{9319a519-0d26-40b3-8af8-c4998becf1c7}_prefwidth=15 maxuncoupledlength=220
DiffPairsRouting DiffPairsRouting_90E [InDifferentialPairClass('DIFF_90E')] p2: maxlimit=5 minlimit=1 mostfreqgap=5 toplayer_mingap=4.5 toplayer_maxgap=4.5 toplayer_prefgap=4.5 toplayer_minwidth=4 toplayer_maxwidth=4 toplayer_prefwidth=4 midlayer1_mingap=5 midlayer1_minwidth=5 midlayer1_maxwidth=5 midlayer1_prefwidth=5 midlayer2_maxgap=1 midlayer2_prefgap=1 midlayer2_minwidth=1 midlayer2_maxwidth=1 midlayer2_prefwidth=1 midlayer3_maxgap=1 midlayer3_prefgap=1 midlayer3_minwidth=1 midlayer3_maxwidth=1 midlayer3_prefwidth=1 midlayer4_maxgap=1 midlayer4_prefgap=1 midlayer4_minwidth=1 midlayer4_maxwidth=1 midlayer4_prefwidth=1 midlayer6_mingap=5 midlayer6_minwidth=4 midlayer6_maxwidth=4 midlayer6_prefwidth=4 midlayer7_mingap=5 midlayer7_minwidth=4 midlayer7_maxwidth=4 midlayer7_prefwidth=4 bottomlayer_mingap=4.5 bottomlayer_maxgap=4.5 bottomlayer_prefgap=4.5 bottomlayer_minwidth=4 bottomlayer_maxwidth=4 bottomlayer_prefwidth=4 substack1={9319A519-0D26-40B3-8AF8-C4998BECF1C7} toplayer_{9319a519-0d26-40b3-8af8-c4998becf1c7}_minwidth=15 toplayer_{9319a519-0d26-40b3-8af8-c4998becf1c7}_maxwidth=15 toplayer_{9319a519-0d26-40b3-8af8-c4998becf1c7}_prefwidth=15 midlayer1_{9319a519-0d26-40b3-8af8-c4998becf1c7}_minwidth=15 midlayer1_{9319a519-0d26-40b3-8af8-c4998becf1c7}_maxwidth=15 midlayer1_{9319a519-0d26-40b3-8af8-c4998becf1c7}_prefwidth=15 midlayer2_{9319a519-0d26-40b3-8af8-c4998becf1c7}_minwidth=15 midlayer2_{9319a519-0d26-40b3-8af8-c4998becf1c7}_maxwidth=15 midlayer2_{9319a519-0d26-40b3-8af8-c4998becf1c7}_prefwidth=15 midlayer3_{9319a519-0d26-40b3-8af8-c4998becf1c7}_minwidth=15 midlayer3_{9319a519-0d26-40b3-8af8-c4998becf1c7}_maxwidth=15 midlayer3_{9319a519-0d26-40b3-8af8-c4998becf1c7}_prefwidth=15 midlayer4_{9319a519-0d26-40b3-8af8-c4998becf1c7}_minwidth=15 midlayer4_{9319a519-0d26-40b3-8af8-c4998becf1c7}_maxwidth=15 midlayer4_{9319a519-0d26-40b3-8af8-c4998becf1c7}_prefwidth=15 midlayer6_{9319a519-0d26-40b3-8af8-c4998becf1c7}_minwidth=15 midlayer6_{9319a519-0d26-40b3-8af8-c4998becf1c7}_maxwidth=15 midlayer6_{9319a519-0d26-40b3-8af8-c4998becf1c7}_prefwidth=15 midlayer7_{9319a519-0d26-40b3-8af8-c4998becf1c7}_minwidth=15 midlayer7_{9319a519-0d26-40b3-8af8-c4998becf1c7}_maxwidth=15 midlayer7_{9319a519-0d26-40b3-8af8-c4998becf1c7}_prefwidth=15 bottomlayer_{9319a519-0d26-40b3-8af8-c4998becf1c7}_minwidth=15 bottomlayer_{9319a519-0d26-40b3-8af8-c4998becf1c7}_maxwidth=15 bottomlayer_{9319a519-0d26-40b3-8af8-c4998becf1c7}_prefwidth=15 maxuncoupledlength=200
DiffPairsRouting DiffPairsRouting_120E [InDifferentialPairClass('DIFF_120E')] p3: maxlimit=5.6 minlimit=1 mostfreqgap=1 toplayer_mingap=5.6 toplayer_prefgap=5.6 toplayer_minwidth=4 toplayer_maxwidth=4 toplayer_prefwidth=4 midlayer1_mingap=5 midlayer1_maxgap=5 midlayer1_prefgap=5 midlayer1_minwidth=5 midlayer1_maxwidth=5 midlayer1_prefwidth=5 midlayer2_maxgap=1 midlayer2_minwidth=1 midlayer2_maxwidth=1 midlayer2_prefwidth=1 midlayer3_maxgap=1 midlayer3_minwidth=1 midlayer3_maxwidth=1 midlayer3_prefwidth=1 midlayer4_maxgap=1 midlayer4_minwidth=1 midlayer4_maxwidth=1 midlayer4_prefwidth=1 midlayer6_maxgap=1 midlayer6_minwidth=1 midlayer6_maxwidth=1 midlayer6_prefwidth=1 midlayer7_maxgap=1 midlayer7_minwidth=1 midlayer7_maxwidth=1 midlayer7_prefwidth=1 bottomlayer_mingap=5.6 bottomlayer_prefgap=5.6 bottomlayer_minwidth=4 bottomlayer_maxwidth=4 bottomlayer_prefwidth=4 substack1={9319A519-0D26-40B3-8AF8-C4998BECF1C7} toplayer_{9319a519-0d26-40b3-8af8-c4998becf1c7}_minwidth=15 toplayer_{9319a519-0d26-40b3-8af8-c4998becf1c7}_maxwidth=15 toplayer_{9319a519-0d26-40b3-8af8-c4998becf1c7}_prefwidth=15 midlayer1_{9319a519-0d26-40b3-8af8-c4998becf1c7}_minwidth=15 midlayer1_{9319a519-0d26-40b3-8af8-c4998becf1c7}_maxwidth=15 midlayer1_{9319a519-0d26-40b3-8af8-c4998becf1c7}_prefwidth=15 midlayer2_{9319a519-0d26-40b3-8af8-c4998becf1c7}_minwidth=15 midlayer2_{9319a519-0d26-40b3-8af8-c4998becf1c7}_maxwidth=15 midlayer2_{9319a519-0d26-40b3-8af8-c4998becf1c7}_prefwidth=15 midlayer3_{9319a519-0d26-40b3-8af8-c4998becf1c7}_minwidth=15 midlayer3_{9319a519-0d26-40b3-8af8-c4998becf1c7}_maxwidth=15 midlayer3_{9319a519-0d26-40b3-8af8-c4998becf1c7}_prefwidth=15 midlayer4_{9319a519-0d26-40b3-8af8-c4998becf1c7}_minwidth=15 midlayer4_{9319a519-0d26-40b3-8af8-c4998becf1c7}_maxwidth=15 midlayer4_{9319a519-0d26-40b3-8af8-c4998becf1c7}_prefwidth=15 midlayer6_{9319a519-0d26-40b3-8af8-c4998becf1c7}_minwidth=15 midlayer6_{9319a519-0d26-40b3-8af8-c4998becf1c7}_maxwidth=15 midlayer6_{9319a519-0d26-40b3-8af8-c4998becf1c7}_prefwidth=15 midlayer7_{9319a519-0d26-40b3-8af8-c4998becf1c7}_minwidth=15 midlayer7_{9319a519-0d26-40b3-8af8-c4998becf1c7}_maxwidth=15 midlayer7_{9319a519-0d26-40b3-8af8-c4998becf1c7}_prefwidth=15 bottomlayer_{9319a519-0d26-40b3-8af8-c4998becf1c7}_minwidth=15 bottomlayer_{9319a519-0d26-40b3-8af8-c4998becf1c7}_maxwidth=15 bottomlayer_{9319a519-0d26-40b3-8af8-c4998becf1c7}_prefwidth=15 maxuncoupledlength=270
FabricationTestPointUsage TestPointUsage [All] p1: valid=2 allowmultiple=FALSE
FabricationTestpoint Testpoint [All] p1: side=3 testpointundercomponent=TRUE minsize=40 maxsize=100 preferedsize=60 minholesize=0 maxholesize=40 preferedholesize=32 testpointgrid=1 allowsidetop=TRUE allowsidebottom=TRUE usegrid=TRUE gridtolerance=0.01
FanoutControl Fanout_LCC [IsLCC] p1: bgadir=Out bgaviamode=Centered fanoutstyle=Auto fanoutdirection=Alternating viagrid=1 // Fanout_LCC (Default Rule)
FanoutControl Fanout_BGA [IsBGA] p2: bgadir=Out bgaviamode=Centered fanoutstyle=Auto fanoutdirection=Alternating viagrid=1 // Fanout_BGA (Default Rule)
FanoutControl Fanout_Default [All] p4: bgadir=Out bgaviamode=Centered fanoutstyle=Auto fanoutdirection=Alternating viagrid=1 // Fanout_Default (Default Rule)
FanoutControl Fanout_Small [(CompPinCount < 5)] p5: bgadir=Out bgaviamode=Centered fanoutstyle=Auto fanoutdirection=OutThenIn viagrid=1 // Fanout_Small (Default Rule)
HoleSize [All] p1: absolutevalues=TRUE maxlimit=251 minlimit=3.9 maxpercent=80.000 minpercent=20.000
HoleToHoleClearance [All] p1 off: gap=9 allowstackedmicrovias=TRUE
MatchedLengths ETH_DIFF_DPM [InxSignalClass('ETH_XNETS')] p1: tolerance=2 checknetsindiffpair=TRUE checkdiffpairvsdiffpair=FALSE checkxsignals=FALSE checkothers=FALSE
MatchedLengths CSI2_RX0_DPM [InxSignalClass('CSI2_RX0_XNETS')] p2: tolerance=2 checknetsindiffpair=TRUE checkdiffpairvsdiffpair=FALSE checkxsignals=FALSE checkothers=FALSE
MatchedLengths CSI2_RX1_DPM [InxSignalClass('CSI2_RX1_XNETS')] p3: tolerance=2 checknetsindiffpair=TRUE checkdiffpairvsdiffpair=FALSE checkxsignals=FALSE checkothers=FALSE
MatchedLengths LVDS_MG_DPM [InxSignalClass('LVDS_XNETS')] p4: tolerance=2 checknetsindiffpair=TRUE checkdiffpairvsdiffpair=FALSE checkxsignals=FALSE checkothers=FALSE
MatchedLengths ETH_DIFF_MG [InxSignalClass('ETH_XNETS')] p5: tolerance=12.5 checknetsindiffpair=FALSE checkdiffpairvsdiffpair=TRUE checkxsignals=TRUE checkothers=TRUE
MatchedLengths CSI2_RX0_MG [InxSignalClass('CSI2_RX0_XNETS')] p6: tolerance=12.5 checknetsindiffpair=FALSE checkdiffpairvsdiffpair=TRUE checkxsignals=TRUE checkothers=TRUE
MatchedLengths CSI2_RX1_MG [InxSignalClass('CSI2_RX1_XNETS')] p7: tolerance=12.5 checknetsindiffpair=FALSE checkdiffpairvsdiffpair=TRUE checkxsignals=TRUE checkothers=TRUE
MatchedLengths LVDS_MG [InxSignalClass('LVDS_XNETS')] p8: tolerance=10 checknetsindiffpair=FALSE checkdiffpairvsdiffpair=TRUE checkxsignals=TRUE checkothers=TRUE
MatchedLengths RGMII_TX_MG [InxSignalClass('RGMII_TX_XNETS')] p9: tolerance=10 checknetsindiffpair=FALSE checkdiffpairvsdiffpair=TRUE checkxsignals=TRUE checkothers=TRUE
MatchedLengths RGMII_RX_MG [InxSignalClass('RGMII_RX_XNETS')] p10: tolerance=10 checknetsindiffpair=FALSE checkdiffpairvsdiffpair=TRUE checkxsignals=TRUE checkothers=TRUE
MatchedLengths QSPI_MG [InxSignalClass('QSPI_XNETS')] p11: tolerance=25 checknetsindiffpair=FALSE checkdiffpairvsdiffpair=TRUE checkxsignals=TRUE checkothers=TRUE
MatchedLengths MIPI_TRACE [InxSignalClass('TRACE_XNETS')] p12: tolerance=250 checknetsindiffpair=FALSE checkdiffpairvsdiffpair=TRUE checkxsignals=TRUE checkothers=TRUE
MatchedLengths MSS_SPI_A_MG [InxSignalClass('MSS_SPIA_XNETS')] p13: tolerance=100 checknetsindiffpair=FALSE checkdiffpairvsdiffpair=TRUE checkxsignals=TRUE checkothers=TRUE
MatchedLengths MSS_SPI_B_MG [InxSignalClass('MSS_SPIB_XNETS')] p14: tolerance=100 checknetsindiffpair=FALSE checkdiffpairvsdiffpair=TRUE checkxsignals=TRUE checkothers=TRUE
MatchedLengths RCSS_SPI_A_MG [InxSignalClass('RCSS_SPIA_XNETS')] p15: tolerance=100 checknetsindiffpair=FALSE checkdiffpairvsdiffpair=TRUE checkxsignals=TRUE checkothers=TRUE
MatchedLengths RCSS_SPI_B_MG [InxSignalClass('RCSS_SPIB_XNETS')] p16: tolerance=100 checknetsindiffpair=FALSE checkdiffpairvsdiffpair=TRUE checkxsignals=TRUE checkothers=TRUE
MatchedLengths DBG_SPI_MG [InxSignalClass('DBG_SPI_XNETS')] p17: tolerance=100 checknetsindiffpair=FALSE checkdiffpairvsdiffpair=TRUE checkxsignals=TRUE checkothers=TRUE
MatchedLengths PMIC_SPI_MG [InxSignalClass('PMIC_SPI_XNETS')] p18: tolerance=100 checknetsindiffpair=FALSE checkdiffpairvsdiffpair=TRUE checkxsignals=TRUE checkothers=TRUE
MinimumAnnularRing MinimumAnnularRing_ThermalPadVias [IsVia and InAnyComponent] p1: minimumring=1.9
MinimumAnnularRing [All] p2 off: minimumring=1.9
MinimumSolderMaskSliver MinimumSolderMaskSliver_Logo [InComponentClass('Logo') vs InComponentClass('Logo')] p1: minsoldermaskwidth=0.7
MinimumSolderMaskSliver [All] p2: minsoldermaskwidth=3
PlaneConnect [All] p1: planeconnectstyle=Relief reliefexpansion=10 reliefentries=4 reliefconductorwidth=10 reliefairgap=10
PolygonConnect [All] p1: connectstyle=Direct reliefconductorwidth=10 reliefentries=4 polygonreliefangle="90 Angle" airgapwidth=10
RoutingVias ThermalPadVias [IsVia and InAnyComponent] p1: holewidth=8 width=18 viastyle="Through Hole" minholewidth=3.9 minwidth=7 maxholewidth=22 maxwidth=22
RoutingVias [All] p2: holewidth=8 width=18 viastyle="Through Hole" minholewidth=3.9 minwidth=7 maxholewidth=12 maxwidth=22
SilkToBoardRegionClearance [Not ((IsComment or IsDesignator) And (Hide <> 'False')) and not InRegion(1000,500,4000,800)] p1:
SilkToSilkClearance SilkToSilkClearance_Pb-FreeLogo [(HasFootprint('Pb-Free_Overlay_Medium') OR HasFootprint('Pb-Free_Overlay_Small')) vs (HasFootprint('Pb-Free_Overlay_Medium') OR HasFootprint('Pb-Free_Overlay_Small'))] p1: silktosilkclearance=0
SilkToSilkClearance [All] p2: silktosilkclearance=0
SilkToSolderMaskClearance SilkToComponentPadClearance [(IsPad or IsFill or IsRegion) and InAnycomponent] p1: minsilkscreentomaskgap=3.5 clearancetoexposedcopper=TRUE
SilkToSolderMaskClearance "Silk to Solder Mask Opening" [All] p2: minsilkscreentomaskgap=3 clearancetoexposedcopper=FALSE
SolderMaskExpansion [All] p1: expansion=1.97 istentingtop=FALSE
UnRoutedNet [All] p1: checkbadconnections=TRUE
Width POWER [InNetClass('PWR')] p1: maxlimit=100 minlimit=4 preferedwidth=10 toplayer_maxwidth=50 bottomlayer_minwidth=7 bottomlayer_maxwidth=50 substack1={9319A519-0D26-40B3-8AF8-C4998BECF1C7} minimp=50.000000 maximp=50.000000 favimp=50.000000
Width [All] p2: maxlimit=100 minlimit=4 preferedwidth=10 toplayer_prefwidth=5.5 midlayer6_prefwidth=5.1 midlayer7_prefwidth=5.1 bottomlayer_prefwidth=5.5 substack1={9319A519-0D26-40B3-8AF8-C4998BECF1C7} minimp=50.000000 maximp=50.000000 favimp=50.000000
13 further rules are at their usual default settings.

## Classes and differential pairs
net class UART: DSS_UARTA_RX DSS_UARTA_TX NetR25_1 NetR29_1 RCSS_UARTA_RX RCSS_UARTA_TX SOC_MSS_UARTA_RX SOC_SOP3_SOC_MSS_UARTB_TX SOC_SOP4_SOC_MSS_UARTA_TX
net class MDIO: MDIO_CLK MDIO_DATA
net class I2C: SOC_I2C_SCL SOC_I2C_SDA
component class Shunt: Z1 Z2
component class "Mounting Holes": H1 H2 H3 H4
component class FE1_PWR: C50 C51 C57 C64 C65 C67 C68 C69 C70 C73 C74 C92 C93 C94 C95 C96 C97 C132 C134 C136 C138 C141 C143 C147 C149 C157 C161 C164 C165 C169 C170 C173 C174 C180 L5 L6 L7 L8
component class FE2_IO: C41 C44 C46 C58 C61 C150 C154 R39 R41 R42 R45 R53 R59 R155 R156 R159 R164 R165 R176 R178 R180 R186 R190 R191 R192 R196 R197 R200 TP23 TP24 TP25 TP29 TP30 TP33 TP34 TP36 TP37 TP40 U6
net class XDS_USB: XDSET_1_D_N XDSET_1_D_P XDSET_1_ID
component class XDS110: C76 C80 C90 C91 C194 C195 C204 C205 C208 C210 C218 C221 C222 C225 C228 C236 C237 C238 J11 P2 R62 R64 R65 R67 R69 R71 R72 R73 R75 R77 R78 R79 R80 R82 R211 R212 R228 R229 R230 R231 R232 R233 U9 U19 U22 Y4
component class Label: LBL1
component class AssemblyNote: ZZ1 ZZ2 ZZ3 ZZ4
component class FiducialMark: FID1 FID2 FID3 FID4 FID5 FID6
component class Hardware: "CAUTION HOT SURFACE1" "ESD Susceptible1" FID1 FID2 FID3 FID4 FID5 FID6 H1 H2 H3 H4 LBL1 Logo1 Logo2 LOGO3 Logo4 MP1 MP2 MP3 MP4 ZZ1 ZZ2 ZZ3 ZZ4
component class Logo: Logo2
component class Header: J3 J6 J7 J8 J22 J23 J24 J28 P1 P2
component class FE1_IO: C40 C43 C45 C59 C62 C66 C151 C155 E1 E2 J28 R40 R43 R44 R56 R157 R158 R160 R170 R171 R172 R173 R174 R175 R179 R181 R183 R185 R188 R189 R193 TP20 TP21 TP22 TP26 TP27 TP31 TP32 TP35 TP38 TP39 U5 Y1
component class 2CAN: C3 C5 C7 C30 C35 C38 C117 C119 C121 C129 C130 C152 D6 D7 J4 J5 L13 L14 R18 R23 R33 R38 R147 R163 R169 S2 U13 U16
component class Connectors: J2 J3 J8 J9 R110 R111 R113 R114 R117 R118 R120 R121 R122 R123 R124 R125 R216 R219 R241
component class Enet_Conn: C100 C101 C102 C103 C105 C108 C109 D10 D11 J1 L10 R96 R100 R101 R103 R106 R107 R108 U11 U12
component class Enet_PHY: C16 C17 C98 C99 C104 C106 C107 C110 C111 C112 C113 C114 C182 C242 C243 C244 D3 D4 D5 FB1 J7 R3 R4 R5 R6 R7 R8 R9 R11 R13 R14 R16 R17 R84 R85 R86 R87 R88 R89 R90 R91 R92 R93 R94 R95 R97 R98 R99 R102 R104 R105 R109 R112 R115 R116 R119 R126 R129 R144 R194 R236 R237 S3 TP43 U4 U10 Y2
component class Clock_Buff: C54 C55 C158 C159 L1 R184 R195 R198 R199 R201 R202 R203 U17
component class SOC_FLASH_SOP: C120 C122 J6 J22 J23 J24 J28 R19 R20 R21 R22 R46 R48 R49 R50 R130 R132 R133 R134 R135 R146 R148 R149 R150 R151 R152 R234 R235 R240 U3 U15
component class SOC_PWR: C4 C6 C8 C9 C10 C11 C12 C13 C14 C15 C18 C19 C20 C21 C22 C23 C24 C26 C27 C28 C29 C31 C32 C33 C34 C36 C37 C39 C42 C116 C124 U14
component class SOC_IO: C1 C25 C115 C118 C123 C125 C126 C127 C128 C137 D1 D2 R1 R2 R15 R24 R25 R26 R27 R28 R29 R30 R31 R32 R34 R35 R36 R37 R47 R54 R76 R81 R127 R128 R131 R136 R137 R138 R139 R140 R141 R142 R143 R145 R153 R154 R161 R162 R168 R187 R225 S1 TP2 TP3 TP4 TP5 TP6 TP7 TP8 TP10 TP11 TP12 TP13 TP14 TP15 TP16 TP17 TP18 TP19 U1 Y3
net class CAN: CAN_FD1_RXD CAN_FD1_TXD CAN_FD2_RXD CAN_FD2_TXD
net class FE_HWSYNC: FE1_SYNC_FROM_SOC
net class FE_REFCLK: FE1_MCU_CLK_OUT FE2_MCU_CLK_OUT
net class LVDS: FE1_CSI2_CLK_N FE1_CSI2_CLK_P FE1_CSI2_TX0_N FE1_CSI2_TX0_P FE1_CSI2_TX1_N FE1_CSI2_TX1_P FE1_CSI2_TX2_N FE1_CSI2_TX2_P FE1_CSI2_TX3_N FE1_CSI2_TX3_P FE2_CSI2_CLK_N FE2_CSI2_CLK_P FE2_CSI2_TX0_N FE2_CSI2_TX0_P FE2_CSI2_TX1_N FE2_CSI2_TX1_P FE2_CSI2_TX2_N FE2_CSI2_TX2_P FE2_CSI2_TX3_N FE2_CSI2_TX3_P
net class QSPI: QSPI_D0_FLASH QSPI_D1_FLASH QSPI_D2_FLASH QSPI_D3_FLASH QSPI_nCE_FLASH_A QSPI_SCLK_FLASH SOC_QSPI_CS SOC_QSPI_D0 SOC_QSPI_D1 SOC_QSPI_D2 SOC_QSPI_D3 SOC_QSPI_SCLK
net class RGMII: ETH_TRD_N ETH_TRD_P NetR89_2 NetR95_2 RGMII_RCLK RGMII_RCTL RGMII_RD0 RGMII_RD1 RGMII_RD2 RGMII_RD3 RGMII_TCLK RGMII_TCTL RGMII_TD0 RGMII_TD1 RGMII_TD2 RGMII_TD3 TRD_N TRD_P
net class FE_SPI: FE1_SPI_CLK FE1_SPI_CS0 FE1_SPI_IRQ FE1_SPI_MISO FE1_SPI_MOSI FE2_SPI_CLK FE2_SPI_CS0 FE2_SPI_IRQ FE2_SPI_MISO FE2_SPI_MOSI
net class SOC_40MHz_CLK: CLKM CLKP
net class SOC_PWR: 1V2 1V7 1V8 3V3 NetC124_1
net class PWR: 1V7 NetC85_1 VPP_LDO_OUT
component class Temp: C2 C82 R10 R12 R70 R74 U2 U8
component class PMIC: C77 C78 C79 C84 C86 C87 C89 C197 C198 C199 C200 C201 C202 C211 C213 C219 C223 C230 C231 C232 C233 C234 C235 L18 L19 L21 L22 R83 R209 R210 R218 R220 R221 R223 R224 R226 R227 U21
component class Pre_Reg: C C47 C48 C49 C60 C63 C71 C72 C75 C81 C83 C85 C88 C144 C145 C153 C162 C167 C176 C177 C178 C179 C183 C192 C193 C196 C203 C206 C207 C209 C212 C214 C215 C216 C217 C220 C224 C226 C227 C229 D8 D9 J10 L2 L3 L4 L15 L20 P1 R51 R52 R55 R57 R58 R60 R61 R63 R66 R68 R166 R167 R177 R182 R204 R205 R206 R207 R208 R213 R214 R215 R217 R222 R238 R239 TP1 TP9 TP28 TP41 TP42 U7 U18 U20
net class GENERAL: FE1_GPIO0 FE1_GPIO1 FE1_GPIO2 FE1_SOP1_SYNC_OUT FE1_SYNC_IN FE2_GPIO0 FE2_GPIO1 FE2_GPIO2 FE2_SYNC_IN
net class RF: FE1_RX1 FE1_RX2 FE1_RX3 FE1_RX4 FE2_RX1 FE2_RX2 FE2_RX3 FE2_RX4
net class SPI: FE1_SPI_CLK FE1_SPI_CS0 FE1_SPI_IRQ FE1_SPI_MISO FE1_SPI_MOSI FE2_SPI_CLK FE2_SPI_CS0 FE2_SPI_IRQ FE2_SPI_MISO FE2_SPI_MOSI
component class FE2_PWR: C52 C53 C56 C131 C133 C135 C139 C140 C142 C146 C148 C156 C160 C163 C166 C168 C171 C172 C175 C181 C184 C185 C186 C187 C188 C189 C190 C191 C239 C240 C241 L16 L17 L23
differential pair SOC_LVDS_TX3: +SOC_LVDS_TX3_P -SOC_LVDS_TX3_N
differential pair SOC_LVDS_TX2: +SOC_LVDS_TX2_P -SOC_LVDS_TX2_N
differential pair SOC_LVDS_TX1: +SOC_LVDS_TX1_P -SOC_LVDS_TX1_N
differential pair SOC_LVDS_TX0: +SOC_LVDS_TX0_P -SOC_LVDS_TX0_N
differential pair SOC_LVDS_FRCLK: +SOC_LVDS_FRCLK_P -SOC_LVDS_FRCLK_N
differential pair SOC_LVDS_CLK: +SOC_LVDS_CLK_P -SOC_LVDS_CLK_N
differential pair ETH_TRD: +ETH_TRD_P -ETH_TRD_N
differential pair XDSET_1_D: +XDSET_1_D_P -XDSET_1_D_N
differential pair FE2_CSI2_TX3: +FE2_CSI2_TX3_P -FE2_CSI2_TX3_N
differential pair FE2_CSI2_TX2: +FE2_CSI2_TX2_P -FE2_CSI2_TX2_N
differential pair FE2_CSI2_TX1: +FE2_CSI2_TX1_P -FE2_CSI2_TX1_N
differential pair FE2_CSI2_TX0: +FE2_CSI2_TX0_P -FE2_CSI2_TX0_N
differential pair FE2_CSI2_CLK: +FE2_CSI2_CLK_P -FE2_CSI2_CLK_N
differential pair FE1_CSI2_TX3: +FE1_CSI2_TX3_P -FE1_CSI2_TX3_N
differential pair FE1_CSI2_TX2: +FE1_CSI2_TX2_P -FE1_CSI2_TX2_N
differential pair FE1_CSI2_TX1: +FE1_CSI2_TX1_P -FE1_CSI2_TX1_N
differential pair FE1_CSI2_TX0: +FE1_CSI2_TX0_P -FE1_CSI2_TX0_N
differential pair FE1_CSI2_CLK: +FE1_CSI2_CLK_P -FE1_CSI2_CLK_N
differential pair TRD: +TRD_P -TRD_N
differential pair TRD3: +TRD3_P -TRD3_N
differential pair TRD2: +TRD2_P -TRD2_N
differential pair TRD1: +TRD1_P -TRD1_N

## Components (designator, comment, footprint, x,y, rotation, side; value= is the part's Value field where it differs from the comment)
C1 "GCM155R71C104KA55D" 0402L 3285,3650 r90 top value=0.1uF
C2 "CGA4J3X7R1H225K125AB" 0402L 4795,3465 r270 top value=0.1uF
C3 "GRM1555C1H220FA01D" 0402 370,2825 r270 top value=22pF
C4 "GCM188R70J225KE22D" 0603 3490,2835 r0 top value=2.2uF
C5 "GCM188R71H472KA37D" 0603 455,2775 r0 top value=4700pF
C6 "GCM188R70J225KE22D" 0603 3490,2775 r0 top value=2.2uF
C7 "GRM1555C1H220FA01D" 0402 370,2725 r90 top value=22pF
C8 "GCM155R71C224KE02D" 0402L 3359.76,2680.35 r270 top value=0.22uF
C9 "GCM155R71C104KA55D" 0402L 3412,2664 r270 top value=0.1uF
C10 "GCM155R71C104KA55D" 0402L 3479,2658 r270 top value=0.1uF
C11 "GCM155R71C224KE02D" 0402L 3539.34,2657.93 r270 top value=0.22uF
C12 "GCM155R71C224KE02D" 0402L 3590.39,2656.23 r270 top value=0.22uF
C13 "GCM155R71C224KE02D" 0402L 3280.29,2632.05 r270 top value=0.22uF
C14 "GCM155R71C224KE02D" 0402L 3242.68,2632.05 r270 top value=0.22uF
C15 "GCM155R71C224KE02D" 0402L 3359.76,2593.08 r270 top value=0.22uF
C16 "GCM21BR71A106KE22L" 0805_HV 1130,2550 r270 top value=10uF
C17 "GCM21BR71A106KE22L" 0805_HV 1370,2550 r270 top value=10uF
C18 "CGA2B3X7R1H103K050BB" 0402 3433,2571 r270 top value=0.01uF
C19 "GCM155R71C224KE02D" 0402L 3513.96,2572.78 r90 top value=0.22uF
C20 "GCM155R71C104KA55D" 0402L 3785,2549 r270 top value=0.1uF
C21 "GCM155R71C224KE02D" 0402L 3695.69,2551.05 r180 top value=0.22uF
C22 "GCM155R71C224KE02D" 0402L 3333.1,2525.71 r180 top value=0.22uF
C23 "GCM155R71C224KE02D" 0402L 3608.39,2525.58 r0 top value=0.22uF
C24 "GCM155R71C104KA55D" 0402L 3710.15,2499.87 r180 top value=0.1uF
C25 "GCM188R71C105KA64J" 0603S 3030,2475 r180 top value=1uF
C26 "GCM155R71C224KE02D" 0402L 3725.66,2460.17 r180 top value=0.22uF
C27 "GCM155R71C224KE02D" 0402L 3365,2434.92 r180 top value=0.22uF
C28 "GCM155R71C224KE02D" 0402L 3255.84,2426.35 r0 top value=0.22uF
C29 "CGA2B3X7R1H103K050BB" 0402 3730.98,2417.01 r0 top value=0.01uF
C30 "GRM1555C1H220FA01D" 0402 370,2365 r270 top value=22pF
C31 "GCM155R71C224KE02D" 0402L 3695.09,2373.58 r180 top value=0.22uF
C32 "GCM155R71C224KE02D" 0402L 3255.89,2373.38 r0 top value=0.22uF
C33 "CGA2B3X7R1H103K050BB" 0402 3371,2350 r0 top value=0.01uF
C34 "GCM155R71C224KE02D" 0402L 3580,2350 r0 top value=0.22uF
C35 "GCM188R71H472KA37D" 0603 455,2315 r0 top value=4700pF
C36 "GCM155R71C224KE02D" 0402L 3514.19,2303 r270 top value=0.22uF
C37 "GCM155R71C224KE02D" 0402L 3437.83,2303 r270 top value=0.22uF
C38 "GRM1555C1H220FA01D" 0402 370,2265 r90 top value=22pF
C39 "GCM155R71C224KE02D" 0402L 3590.54,2240.88 r90 top value=0.22uF
C40 "GCM21BR71A106KE22L" 0805_HV 2835,2185 r90 top value=10uF
C41 "GCM21BR71A106KE22L" 0805_HV 4705,2185 r90 top value=10uF
C42 "GCM155R71C224KE02D" 0402L 3475.39,2219.26 r270 top value=0.22uF
C43 "GCM155R71C224KE02D" 0402 2725,2165 r90 top value=0.22uF
C44 "GCM155R71C224KE02D" 0402 4590,2165 r90 top value=0.22uF
C45 "GCM155R71C224KE02D" 0402L 2770,2165 r90 top value=0.22uF
C46 "GCM155R71C224KE02D" 0402L 4635,2165 r90 top value=0.22uF
C47 "GRM155R70J105MA12D" 0402 810,2120 r180 top value=1uF
C48 "C1005X7S1A225K050BC" 0402_065L 680,2045 r90 top value=2.2uF
C49 "C0402C330J5GAC" 0402L 890,2025 r270 top value=33pF
C50 "GCM155R71C224KE02D" 0402L 2210,2005 r270 top value=0.22uF
C51 "GCM155R71C224KE02D" 0402L 2245,2005 r270 top value=0.22uF
C52 "GCM155R71C224KE02D" 0402L 4055,1990 r270 top value=0.22uF
C53 "GCM155R71C224KE02D" 0402L 4090,1990 r270 top value=0.22uF
C54 "GCM21BR71A106KE22L" 0805_HV 3310,1860 r90 top value=10uF
C55 "C2012X7R1C225K125AB" 0805_HV 3390,1860 r270 top value=10uF
C56 "GCM155R71C224KE02D" 0402L 4110,1880 r90 top value=0.22uF
C57 "GCM155R71C224KE02D" 0402L 2215,1810 r270 top value=0.22uF
C58 "GCM188R71C105KA64D" 0603 4540,1680 r270 top value=1uF
C59 "GCM188R71C105KA64D" 0603 2678,1668 r270 top value=1uF
C60 "CGA4J3X7R1H225K125AB" 0805_HV 590,1640 r90 top value=2.2uF
C61 "0402YC101KAT2A" 0402 4345,1690 r180 top value=100pF
C62 "GJM1555C1H4R7BB01D" 0402 2353.61,1646.19 r270 top value=4.7pF
C63 "CGA4J3X7R1H225K125AB" 0805_HV 1115.98,1590.56 r0 top value=2.2uF
C64 "GCM155R71C224KE02D" 0402L 1775,1575 r0 top value=0.22uF
C65 "GCM155R71C224KE02D" 0402L 1965,1575 r0 top value=0.22uF
C66 "GJM1555C1H4R7BB01D" 0402 2446.72,1550.6 r180 top value=4.7pF
C67 "GCM188R71C105KA64J" 0603S 1775,1535 r0 top value=1uF
C68 "GCM188R71C105KA64J" 0603S 1960,1535 r0 top value=1uF
C69 "GCM21BR71A106KE22L" 0805L 1775,1475 r0 top value=10uF
C70 "GCM21BR71A106KE22L" 0805L 1965,1475 r0 top value=10uF
C71 "CGA4J3X7R1H225K125AB" 0805_HV 1115.98,1445 r0 top value=2.2uF
C72 "C3216X7R1H475K160AC" 1206_180 1245,1399.8 r90 top value=4.7uF
C73 "GCM21BD70J226ME36L" 0805 1775,1400 r0 top value=22uF
C74 "GCM21BD70J226ME36L" 0805 1965,1400 r0 top value=22uF
C75 "CGA4J3X7R1H225K125AB" 0805_HV 345,1015 r180 top value=2.2uF
C76 "C0402C104K8RACTU" 0402L 2680,930 r0 top value=0.1uF
C77 "NFM18HC105C1C3D" FP-NFM18HC105C1C3D_0603-MFG 1955,890 r0 bottom
C78 "GCM21BR71A106KE22L" 0805_HV 1860,840 r270 top value=10uF
C79 "GCM21BR71A106KE22L" 0805_HV 2050,840 r270 top value=10uF
C80 "GCM155C71A105KE38D" 0402_070 2680,895 r180 top value=1uF
C81 "C3216X7R1H475K160AC" 1206_180 295.22,820 r270 top value=4.7uF
C82 "C0402C104K8RACTU" 0402L 1685,815 r90 top value=0.1uF
C83 "CGA3E2C0G1H100D080AA" 0603 745,775 r180 top value=10pF
C84 "GCM188R70J225KE22D" 0603S 1760.47,695 r180 bottom value=2.2uF
C85 "CGA3E3X8R1H104K080AB" 0603 480,675 r180 top value=0.1uF
C86 "GCM21BR71A106KE22L" 0805_HV 1860,580 r90 top value=10uF
C87 "GCM21BR71A106KE22L" 0805_HV 2050,580 r90 top value=10uF
C88 "CGA3E3X8R1H104K080AB" 0603 480,615 r180 top value=0.1uF
C89 "NFM18HC105C1C3D" FP-NFM18HC105C1C3D_0603-MFG 1955,530 r0 bottom
C90 "C0402C104K8RACTU" 0402L 2770,510 r180 top value=0.1uF
C91 "C0402C103K4RACTU" 0402L 2770,475 r180 top value=0.01uF
C92 "GCM21BD70J226ME36L" 0805 1935,215 r90 top value=22uF
C93 "GCM21BR71A106KE22L" 0805L 2020,215 r90 top value=10uF
C94 "GCM188R71C105KA64J" 0603S 2080,215 r90 top value=1uF
C95 "GCM21BD70J226ME36L" 0805 2495,115 r270 top value=22uF
C96 "GCM21BR71A106KE22L" 0805L 2575,115 r270 top value=10uF
C97 "GCM188R71C105KA64J" 0603S 2635,115 r270 top value=1uF
C98 "GCM21BR71A106KE22L" 0805_HV 1660,3745 r180 bottom value=10uF
C99 "GCM155R71C104KA55D" 0402L 1660,3630 r0 bottom value=0.1uF
C100 "GRM1555C1H470FA01D" 0402 1430,3500 r270 bottom value=47pF
C101 "GRM1555C1H220FA01D" 0402 1515,3445 r270 bottom value=22pF
C102 "CGA4J2X7R2A104K125AA" 0805_HV 1025,3435 r0 bottom value=0.1uF
C103 "CGA4J2X7R2A104K125AA" 0805_HV 1025,3355 r0 bottom value=0.1uF
C104 "CGA3E3X7R1H474K080AE" 0603 2050,3325 r270 bottom value=0.47uF
C105 "GRM1555C1H220FA01D" 0402 1515,3345 r270 bottom value=22pF
C106 "GCM155R71C104KA55D" 0402L 1954,3342 r90 bottom value=0.1uF
C107 "GCM155R71C104KA55D" 0402L 1594,3310 r90 bottom value=0.1uF
C108 "GRM1555C1H470FA01D" 0402 1430,3290 r270 bottom value=47pF
C109 "GCM216R71H472KA37D" 0805_HV 970,3250 r0 bottom value=4700pF
C110 "CGA3E3X7R1H474K080AE" 0603 1555,3195 r0 bottom value=0.47uF
C111 "GCM155R71C104KA55D" 0402L 1673,3250 r0 bottom value=0.1uF
C112 "CGA2B3X7R1H103K050BB" 0402 2000,3324.1 r270 bottom value=0.01uF
C113 "GCM1555C1H270JA16D" 0402 1824,3052 r0 bottom value=27pF
C114 "GCM1555C1H270JA16D" 0402 1724,3052 r180 bottom value=27pF
C115 "GJM1555C1H4R7BB01D" 0402 3135,2865 r135 bottom value=4.7pF
C116 "GCM188R70J225KE22D" 0603 3765,2795 r270 bottom value=2.2uF
C117 "0402YC104KAT2A" 0402S 835,2785 r90 bottom value=0.1uF
C118 "GJM1555C1H4R7BB01D" 0402 3100,2700 r225 bottom value=4.7pF
C119 "0402YC104KAT2A" 0402S 850,2690 r270 bottom value=0.1uF
C120 "GCM188R71C105KA64D" 0603 2025,2635 r90 bottom value=1uF
C121 "0402YC104KAT2A" 0402S 590,2675 r180 bottom value=0.1uF
C122 "CGA2B3X7R1H104K050BB" 0402L 1975,2645 r90 bottom value=0.1uF
C123 "GCM188R71C105KA64J" 0603S 3050,2620 r180 bottom value=1uF
C124 "CGA2B3X7R1H473K050BB" 0402 3150,2615 r180 bottom value=0.047uF
C125 "GCM188R71C105KA64J" 0603S 3045,2549.71 r90 bottom value=1uF
C126 "GCM188R71C105KA64J" 0603S 3115.69,2555.97 r180 bottom value=1uF
C127 "GCM188R71C105KA64J" 0603S 3030,2480 r180 bottom value=1uF
C128 "GCM188R71C105KA64J" 0603S 3030,2430 r180 bottom value=1uF
C129 "0402YC104KAT2A" 0402S 790,2315 r90 bottom value=0.1uF
C130 "0402YC104KAT2A" 0402S 660,2225 r0 bottom value=0.1uF
C131 "GCM21BR71A106KE22L" 0805_HV1 4439.52,2198.59 r0 bottom value=10uF
C132 "GCM21BR71A106KE22L" 0805_HV1 2545,2180 r0 bottom value=10uF
C133 "GCM21BR71A106KE22L" 0805 4590,2140 r90 bottom value=10uF
C134 "GCM21BR71A106KE22L" 0805 2725,2140 r90 bottom value=10uF
C135 "GCM21BR71A106KE22L" 0805_HV 4235,2135 r180 bottom value=10uF
C136 "GCM21BR71A106KE22L" 0805_HV 2365,2135 r180 bottom value=10uF
C137 "UMK105B7222KV-F" 0402 1495,2150 r0 bottom value=2200pF
C138 "GCM155R71C224KE02D" 0402 2600.98,2072.01 r270 bottom value=0.22uF
C139 "GCM155R71C224KE02D" 0402 4470,2070 r270 bottom value=0.22uF
C140 "GCM155R71C224KE02D" 0402L 4410,2080 r0 bottom value=0.22uF
C141 "GCM155R71C224KE02D" 0402L 2545,2080 r0 bottom value=0.22uF
C142 "GCM155R71C224KE02D" 0402L 4257,2070 r180 bottom value=0.22uF
C143 "GCM155R71C224KE02D" 0402L 2395,2070 r180 bottom value=0.22uF
C144 "885012205055" 0402 1045,2025 r90 bottom value=100pF
C145 "GRM155R71H471KA01D" 0402 995,2025 r90 bottom value=470pF
C146 "GCM155R71C224KE02D" 0402L 4355,2035 r270 bottom value=0.22uF
C147 "GCM155R71C224KE02D" 0402L 2490,2033 r270 bottom value=0.22uF
C148 "GCM155R71C224KE02D" 0402 4404,2000 r270 bottom value=0.22uF
C149 "GCM155R71C224KE02D" 0402 2540,2000 r270 bottom value=0.22uF
C150 "GCM188R71C105KA64D" 0603 4490,1970 r180 bottom value=1uF
C151 "GCM188R71C105KA64D" 0603 2625,1970 r180 bottom value=1uF
C152 "GRM188R71H103KA01D" 0603 1500,1950 r0 bottom value=0.01uF
C153 "GCM155R71C104KA55D" 0402L 1185,1920 r270 bottom value=0.1uF
C154 "CGA2B3X7R1H473K050BB" 0402 4465,1920 r180 bottom value=0.047uF
C155 "CGA2B3X7R1H473K050BB" 0402 2605,1920 r180 bottom value=0.047uF
C156 "GCM155R71C224KE02D" 0402L 4225,1890 r90 bottom value=0.22uF
C157 "GCM155R71C224KE02D" 0402L 2362,1890 r90 bottom value=0.22uF
C158 "CGA2B3X7R1H104K050BB" 0402 3365,1850 r270 bottom value=2.2uF
C159 "C0402C104K8RACTU" 0402L 3405,1850 r90 bottom value=0.1uF
C160 "GCM155R71C224KE02D" 0402 4560,1860 r0 bottom value=0.22uF
C161 "GCM155R71C224KE02D" 0402 2700,1865 r0 bottom value=0.22uF
C162 "GRM188R71A225KE15J" 0603 930,1850 r180 bottom value=2.2uF
C163 "GCM155R71C224KE02D" 0402 4314.37,1847.01 r0 bottom value=0.22uF
C164 "GCM155R71C224KE02D" 0402 2573,1847 r180 bottom value=0.22uF
C165 "GCM155R71C224KE02D" 0402 2450.98,1847.01 r0 bottom value=0.22uF
C166 "GCM155R71C224KE02D" 0402 4436,1847 r180 bottom value=0.22uF
C167 "GCM188R71H104KA57D" 0603L 1195,1815 r90 bottom value=0.1uF
C168 "GCM21BR71A106KE22L" 0805_HV 4590,1760 r270 bottom value=10uF
C169 "GCM21BR71A106KE22L" 0805_HV 2750,1760 r270 bottom value=10uF
C170 "GCM155R71C104KA55D" 0402 2255,1780 r270 bottom value=0.1uF
C171 "GCM155R71C224KE02D" 0402L 4455,1780 r270 bottom value=0.22uF
C172 "GCM155R71C224KE02D" 0402L 4405,1780 r270 bottom value=0.22uF
C173 "GCM155R71C224KE02D" 0402L 2590,1780 r270 bottom value=0.22uF
C174 "GCM155R71C224KE02D" 0402L 2540,1780 r270 bottom value=0.22uF
C175 "GCM155R71C104KA55D" 0402L 4205,1775 r270 bottom value=0.1uF
C176 "GCM32ER71E106KA57L" 1210_280 910,1720 r270 bottom value=10uF
C177 "GCM32ER71E106KA57L" 1210_280 770,1720 r270 bottom value=10uF
C178 "GCM32ER71E106KA57L" 1210_280 630,1720 r270 bottom value=10uF
C179 "GCM188R71E105KA64D" 0603L 995,1755 r270 bottom value=1uF
C180 "GCM155R71C104KA55D" 0402L 2330,1765 r270 bottom value=0.1uF
C181 "GCM155R71C104KA55D" 0402 4115,1745 r270 bottom value=0.1uF
C182 "UMK105B7222KV-F" 0402 1490,1750 r180 bottom value=2200pF
C183 "GRM188R71A225KE15J" 0603 1085,1710 r180 bottom value=2.2uF
C184 "GCM155R71C224KE02D" 0402L 2145,1580 r180 bottom value=0.22uF
C185 "GCM155R71C224KE02D" 0402L 1980,1575 r0 bottom value=0.22uF
C186 "GCM188R71C105KA64J" 0603S 2145,1540 r180 bottom value=1uF
C187 "GCM188R71C105KA64J" 0603S 1980,1535 r0 bottom value=1uF
C188 "GCM21BR71A106KE22L" 0805L 2145,1480 r180 bottom value=10uF
C189 "GCM21BR71A106KE22L" 0805L 1980,1475 r0 bottom value=10uF
C190 "GCM21BD70J226ME36L" 0805 2145,1405 r180 bottom value=22uF
C191 "GCM21BD70J226ME36L" 0805 1980,1400 r0 bottom value=22uF
C192 "CO4" 1210_280 1165,1240 r180 bottom value=22uF
C193 "GRM32ER71H106KA12L" 1210_270 965,1215 r0 bottom value=10uF
C194 "GCM1555C1H8R0DA16D" 0402 2750,1220 r0 bottom
C195 "GCM1555C1H8R0DA16D" 0402 2855,1130.35 r270 bottom
C196 "CO2" 1210_280 1165,1120 r180 bottom value=22uF
C197 "GCM21BD70J226ME36L" 0805 2210,1085 r90 bottom value=22uF
C198 "GCM21BD70J226ME36L" 0805 2130,1085 r90 bottom value=22uF
C199 "GCM21BD70J226ME36L" 0805 2050,1085 r90 bottom value=22uF
C200 "GCM21BD70J226ME36L" 0805 1860,1085 r90 bottom value=22uF
C201 "GCM21BD70J226ME36L" 0805 1780,1085 r90 bottom value=22uF
C202 "GCM21BD70J226ME36L" 0805 1700,1085 r90 bottom value=22uF
C203 "CGA4J3X7R1H225K125AB" 0805_HV 965,1105 r0 bottom value=2.2uF
C204 "C0402C104K8RACTU" 0402L 2440,1100 r0 bottom value=0.1uF
C205 "C0402C104K8RACTU" 0402L 2610,1065 r180 bottom value=0.1uF
C206 "CGA3E3X7R1H474K080AE" 0603 965,1030 r0 bottom value=0.47uF
C207 "CO5" 0805_HV 1165,1015 r180 bottom value=1uF
C208 "C0402C104K8RACTU" 0402L 2950,1005 r180 bottom value=0.1uF
C209 "C1608X7R1H154K080AB" 0603 965,975 r0 bottom value=0.15uF
C210 "C0402C103K4RACTU" 0402S 2990,900 r90 bottom value=0.01uF
C211 "GCM155R71C104KA55D" 0402L 1770,815 r180 bottom value=0.1uF
C212 "CBIAS" 0603 740,785 r0 bottom value=1uF
C213 "GCM155C71A474KE36D" 0402S 1785,750 r90 bottom value=0.47uF
C214 "C1608X7R1H154K080AB" 0603 965,725 r0 bottom value=0.15uF
C215 "GCM155R71C104KA55D" 0402L 770,715 r90 bottom value=0.1uF
C216 "CO4" 1210_280 1165,665 r180 bottom value=22uF
C217 "CBOOT" 0603L 835,700 r180 bottom value=0.1uF
C218 "GCM155C71A105KE38D" 0402_070 2270,685 r90 bottom value=1uF
C219 "GCM155C71A474KE36D" 0402S 1790,640 r90 bottom value=0.47uF
C220 "CGA3E3X7R1H474K080AE" 0603 965,670 r0 bottom value=0.47uF
C221 "C1005X7S1A225K050BC" 0402_065L 3025,625 r90 bottom value=2.2uF
C222 "C0402C104K8RACTU" 0402L 2990,625 r90 bottom value=0.1uF
C223 "GCM155R71C104KA55D" 0402L 1735,620 r270 bottom value=0.1uF
C224 "CGA4J3X7R1H225K125AB" 0805_HV 965,600 r0 bottom value=2.2uF
C225 "C0402C104K8RACTU" 0402L 2270,590 r270 bottom value=0.1uF
C226 "CO1" 1210_280 1165,545 r180 bottom value=22uF
C227 "GRM32ER71H106KA12L" 1210_270 965,495 r0 bottom value=10uF
C228 "GCM155C71A105KE38D" 0402_070 2990,530 r270 bottom value=1uF
C229 "CO3" 1210_280 1165,425 r180 bottom value=22uF
C230 "GCM21BD70J226ME36L" 0805 2210,335 r270 bottom value=22uF
C231 "GCM21BD70J226ME36L" 0805 2130,335 r270 bottom value=22uF
C232 "GCM21BD70J226ME36L" 0805 2050,335 r270 bottom value=22uF
C233 "GCM21BD70J226ME36L" 0805 1860,335 r270 bottom value=22uF
C234 "GCM21BD70J226ME36L" 0805 1780,335 r270 bottom value=22uF
C235 "GCM21BD70J226ME36L" 0805 1700,335 r270 bottom value=22uF
C236 "CL21B106KOQNNNE" 0805_HV 790,325 r180 bottom value=10uF
C237 "C0402C104K8RACTU" 0402L 2445,340 r0 bottom value=0.1uF
C238 "C0402C103K4RACTU" 0402L 2915,339.25 r180 bottom value=0.01uF
C239 "GCM21BD70J226ME36L" 0805 2495,115 r270 bottom value=22uF
C240 "GCM21BR71A106KE22L" 0805L 2575,115 r270 bottom value=10uF
C241 "GCM188R71C105KA64J" 0603S 2635,115 r270 bottom value=1uF
C242 "CGA2B3X7R1H103K050BB" 0402 1555,3245 r0 bottom value=0.01uF
C243 "GCM188R71C105KA64J" 0603S 1660,3675 r180 bottom value=1uF
C244 "CGA2B3X7R1H103K050BB" 0402 1690,3586 r180 bottom value=0.01uF
"CAUTION HOT SURFACE1" "CAUTION HOT SURFACE" IEC_HotSurface_Small 1617.5,2564.6 r0 top
D1 "SML-P12YTT86" LED_SMLP12_YELLOW 3335,3865 r90 top value=Yellow
D2 "SML-P12DTT86" LED_SMLP12_ORANGE 3385,3865 r90 top value=Orange
D3 "SML-P12DTT86" LED_SMLP12_ORANGE 395,3860 r270 top value=Orange
D4 "SML-P12YTT86" LED_SMLP12_YELLOW 500,3860 r270 top value=Yellow
D5 "SML-P12PTT86" SML-P1_GREEN 600,3860 r90 top value=Green
D6 "PESD1CAN,215" SOT-23 270,2775 r0 top value=24V
D7 "PESD1CAN,215" SOT-23 270,2315 r0 top value=24V
D8 "FSV530AF" SMAF 480,855 r0 top value=30V
D9 "ATV02W280B-HF" SOD-123 480,755 r0 top value=28V
D10 "TPD1E05U06QDPYRQ1" DPY0002A 875,3419 r90 bottom
D11 "TPD1E05U06QDPYRQ1" DPY0002A 875,3371 r270 bottom
E1 "RX Antenna" "RX Antenna" 2535.1,2702.17 r0 top locked
E2 "TX Antenna" "TX Antenna" 3330.57,1221.85 r0 top
"ESD Susceptible1" "ESD Susceptible" ESD_Overlay_Small 390,3055 r0 top
FB1 "BLM18KG601SH1" "FP-BLM18KG601SH1_0603 (1608 Metric)-MFG" 1695,3845 r270 bottom
FID1 "Fiducial" Fiducial10-20 78.74,3858.27 r90 top
FID2 "Fiducial" Fiducial10-20 4685.04,3858.27 r90 top
FID3 "Fiducial" Fiducial10-20 78.74,78.74 r90 top
FID4 "Fiducial" Fiducial10-20 78.74,3858.27 r90 bottom
FID5 "Fiducial" Fiducial10-20 4685.04,3858.27 r90 bottom
FID6 "Fiducial" Fiducial10-20 78.74,78.74 r90 bottom
H1 "NY PMS 440 0025 PH" "NY PMS 440 0025 PH" 1023.62,3752.17 r0 top
H2 "NY PMS 440 0025 PH" "NY PMS 440 0025 PH" 4921.26,3752.17 r0 top
H3 "NY PMS 440 0025 PH" "NY PMS 440 0025 PH" 1496.06,1468.7 r0 top
H4 "NY PMS 440 0025 PH" "NY PMS 440 0025 PH" 4921.26,208.86 r0 top
J1 "9-2304372-9" TE_9-2304372-9 207.24,3395.01 r90 bottom
J2 "QSH-030-01-L-D-A" Samtec_QSH-030-01-X-D-A 3365,3225 r90 bottom
J3 "FTR-110-51-S-D-06" Samtec_FTR-110-51-x-D-06 4715,3075 r180 bottom
J4 "1727010" PhoenixConact_1727010 142.24,2777.01 r90 bottom
J5 "1727010" PhoenixConact_1727010 142.24,2317.01 r90 bottom
J6 "TSW-103-07-G-S" TSW-103-07-X-S 400,1850 r270 bottom
J7 "TSW-103-07-G-S" TSW-103-07-X-S 250,1850 r270 bottom
J8 "TSW-103-07-G-S" TSW-103-07-X-S 100,1850 r270 bottom
J9 "SSW-112-01-L-T" FP-SSW-112-01-L-T_HDR36-MFG 1475.98,667.01 r270 bottom locked
J10 "PJ-063AH" CUI_PJ-063AH 302.24,457.01 r180 bottom
J11 "105017-0001" CONN_105017-0001 815,110 r180 bottom
L1 "BLM18SG121TN1D" 0603 3350,1740 r0 top value="120 ohm"
L2 "HR2220V801R-10" 2220_390 830,1512.01 r0 top value="800 ohm"
L3 "ACM1211-701-2PL-TL01" TDK_ACM1211 307.36,1347.6 r180 top
L4 "XGL4030-102MEC" FP-XGL4030-102MEC_SMD_IND_4MM0_4MM0-MFG 955,1285 r270 top value=1uH
L5 "NLCV32T-R10M-EFRD" NLCV32 1720,1265 r90 top value=100nH
L6 "NLCV32T-R10M-EFRD" NLCV32 1910,1265 r90 top value=100nH
L7 "NLCV32T-R10M-EFRD" NLCV32 2360,170 r0 top value=100nH
L8 "MPZ2012S300AT000" MPZ2012 1830,185 r0 top value="30 ohm"
L10 "ACT1210-101-2P-TL00" TDK_ACT1210 1195,3395 r180 bottom value=100uH
L13 "ACT45B-101-2P-TL003" ACT45B 490,2775 r180 bottom value=100uH
L14 "ACT45B-101-2P-TL003" ACT45B 489.59,2315 r180 bottom value=100uH
L15 "XEL4030-471MEB" XEL4030_310 1315,1725 r180 bottom value=470nH
L16 "NLCV32T-R10M-EFRD" NLCV32 2175,1265 r90 bottom value=100nH
L17 "NLCV32T-R10M-EFRD" NLCV32 1950,1265 r90 bottom value=100nH
L18 "TFM252012ALMAR47MTAA" FP-TFM252012ALMAR47MTAA_1008-MFG 2060,920 r90 bottom value=0.47uH
L19 "TFM252012ALMAR47MTAA" FP-TFM252012ALMAR47MTAA_1008-MFG 1850,920 r90 bottom value=0.47uH
L20 "XAL5020-561MEB" XAL5020 1165,850 r0 bottom value=560nH
L21 "TFM252012ALMAR47MTAA" FP-TFM252012ALMAR47MTAA_1008-MFG 2060,500 r270 bottom value=0.47uH
L22 "TFM252012ALMAR47MTAA" FP-TFM252012ALMAR47MTAA_1008-MFG 1850,500 r270 bottom value=0.47uH
L23 "NLCV32T-R10M-EFRD" NLCV32 2360,170 r0 bottom value=100nH
LBL1 "THT-14-423-10" Label_650x200 3365,3395 r0 top value=TPR12EVM
Logo1 "FCC disclaimer" FCC_disclaimer -829.02,3977.01 r0 top
Logo2 "Texas Instruments" TI_Stacked_Overlay_Small 1300,3250 r0 top
LOGO3 "CE Mark" CE_Mark_5mm 855.69,2565.17 r0 top
Logo4 "WEEE logo" WEEE_Minimum 145,3095 r0 top
MP1 "1902D" FP-1902D_HEX_STANDOFF_#4-40-MFG 4921.26,3752.17 r180 bottom
MP2 "1902D" FP-1902D_HEX_STANDOFF_#4-40-MFG 1023.62,3752.17 r180 bottom
MP3 "1902D" FP-1902D_HEX_STANDOFF_#4-40-MFG 1496.06,1468.7 r180 bottom
MP4 "1902D" FP-1902D_HEX_STANDOFF_#4-40-MFG 4921.26,208.86 r180 bottom
P1 "TSW-102-07-G-S" TSW-102-07-G-S 1055,2180 r180 bottom
P2 "TSW-102-07-G-S" TSW-102-07-G-S 2755,290 r180 bottom
R1 "ERJ-2RKF4700X" 0402 3335,3775 r270 top value=470
R2 "ERJ-2RKF4700X" 0402 3385,3775 r270 top value=470
R3 "CRCW04022K49FKED" 0402 1765,3680 r90 top value=2.49k
R4 "CRCW04022K49FKED" 0402 1810,3680 r90 top value=2.49k
R5 "CRCW04022K49FKED" 0402 1855,3680 r90 top value=2.49k
R6 "CRCW04022K49FKED" 0402 1900,3680 r90 top value=2.49k
R7 "CRCW04022K49FKED" 0402 1575,3590 r180 top value=2.49k
R8 "CRCW04022K49FKED" 0402 1565,3520 r90 top value=2.49k
R9 "CRCW04022K49FKED" 0402 1520,3475 r90 top value=2.49k
R10 "CRCW040210K0FKED" 0402L 4620,3445 r270 top value=10.0k
R11 "CRCW04022K20JNED" 0402 1965,3345 r90 top value=2.2k
R12 "CRCW04020000Z0ED" 0402 4724.37,3375 r180 top value=0
R13 "CRCW04022K49FKED" 0402 1835,3364 r0 top value=2.49k
R14 "CRCW04022K49FKED" 0402 1745,3334.43 r90 top value=2.49k
R15 "CRCW04022K20JNED" 0402 2115,3320 r0 top value=2.2k
R16 "CRCW020133R2FNED" 0201_Silk 2025,3320 r180 top value=33.2
R17 "CRCW040210K0FKED" 0402L 1815,3299.69 r270 top value=10.0k
R18 "CRCW040261R9FKED" 0402 455,2850 r0 top value=61.9
R19 "CRCW040210K0JNED" 0402 3400,2795 r270 top value=10k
